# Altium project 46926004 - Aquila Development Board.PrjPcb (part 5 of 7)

## Sheet 225_Debug2.SchDoc: Aquila Development Board
size A3; Organization: Toradex Solutions Inc.; Address1: 6415 Northwest Drive; Address2: Mississauga, ON, L4V 1X1; Address3: Canada; SheetNumber: 11; SheetTotal: 34
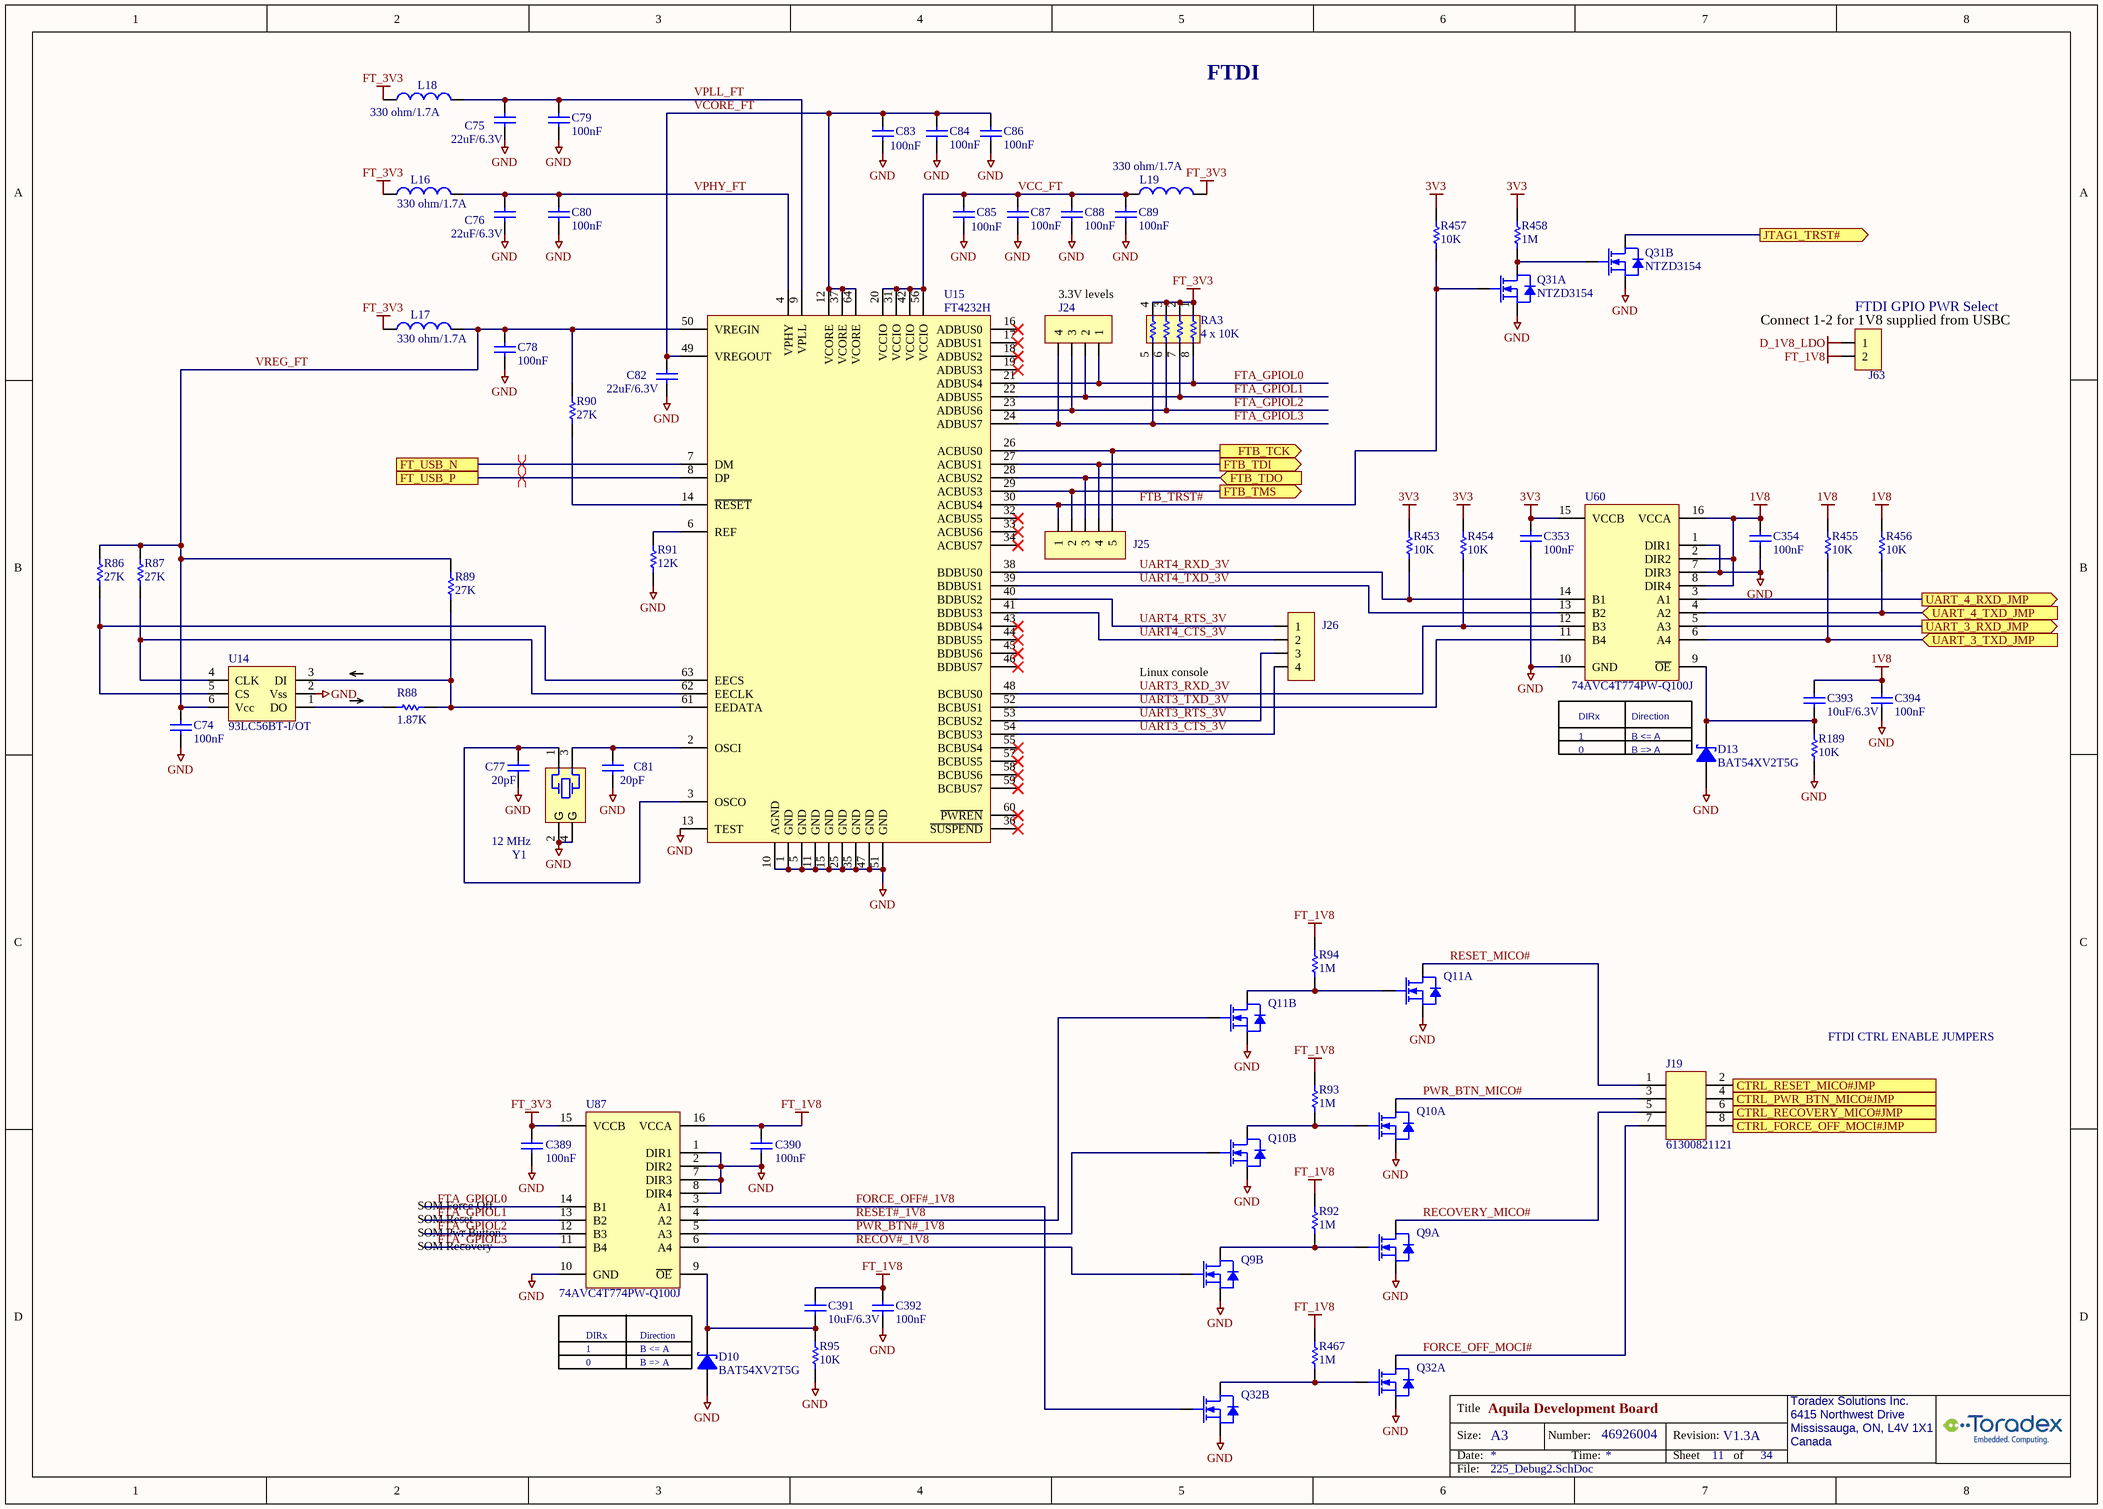
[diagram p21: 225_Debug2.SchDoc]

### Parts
C74  100nF  [C0402_CAPC1005L]
C75  22uF/6.3V  [C0402_CAPC1005L]
C76  22uF/6.3V  [C0402_CAPC1005L]
C77  value 20pF  [C0402_CAPC1005L]  (hidden comment: 1555-Cap-0402-20pF)
C78  100nF  [C0402_CAPC1005L]
C79  100nF  [C0402_CAPC1005L]
C80  100nF  [C0402_CAPC1005L]
C81  value 20pF  [C0402_CAPC1005L]  (hidden comment: 1555-Cap-0402-20pF)
C82  22uF/6.3V  [C0402_CAPC1005L]
C83  100nF  [C0402_CAPC1005L]
C84  100nF  [C0402_CAPC1005L]
C85  100nF  [C0402_CAPC1005L]
C86  100nF  [C0402_CAPC1005L]
C87  100nF  [C0402_CAPC1005L]
C88  100nF  [C0402_CAPC1005L]
C89  100nF  [C0402_CAPC1005L]
C353  100nF  [C0402_CAPC1005L]
C354  100nF  [C0402_CAPC1005L]
C389  100nF  [C0402_CAPC1005L]
C390  100nF  [C0402_CAPC1005L]
C391  value 10uF/6.3V  [C0402_CAPC1005L]  (hidden comment: 1646-Cap-0402-10uF/6.3V)
C392  100nF  [C0402_CAPC1005L]
C393  value 10uF/6.3V  [C0402_CAPC1005L]  (hidden comment: 1646-Cap-0402-10uF/6.3V)
C394  100nF  [C0402_CAPC1005L]
D10  BAT54XV2T5G  [SOD523_SC79]
D13  BAT54XV2T5G  [SOD523_SC79]
J19  61300821121  [WURTH_61300821121]
J24  000-Hdr-4pin  [HDR1X4]  (value not drawn)  (no BOM)
J25  000-Hdr-5pin  [HDR1X5]  (value not drawn)  (no BOM)
J26  000-Hdr-4pin  [HDR1X4]  (value not drawn)  (no BOM)
J63  67996-200HLF  [CON_HDR1X2]  (value not drawn)
L16  value 330 ohm/1.7A  [C/0603]  (hidden comment: 0405-Fer-0603-330ohm/1.7A)
L17  value 330 ohm/1.7A  [C/0603]  (hidden comment: 0405-Fer-0603-330ohm/1.7A)
L18  value 330 ohm/1.7A  [C/0603]  (hidden comment: 0405-Fer-0603-330ohm/1.7A)
L19  value 330 ohm/1.7A  [C/0603]  (hidden comment: 0405-Fer-0603-330ohm/1.7A)
Q9  NTZD3154  [SOT563]  (value not drawn)  (parts A,B of 2)
Q10  NTZD3154  [SOT563]  (value not drawn)  (parts A,B of 2)
Q11  NTZD3154  [SOT563]  (value not drawn)  (parts A,B of 2)
Q31  NTZD3154  [SOT563]  (parts A,B of 2)
Q32  NTZD3154  [SOT563]  (value not drawn)  (parts A,B of 2)
R86  value 27K  [R0402_RESC1005L]  (hidden comment: 1538-Res-0402-27k)
R87  value 27K  [R0402_RESC1005L]  (hidden comment: 1538-Res-0402-27k)
R88  value 1.87K  [R0402_RESC1005L]  (hidden comment: 1536-Res-0402-1.87K)
R89  value 27K  [R0402_RESC1005L]  (hidden comment: 1538-Res-0402-27k)
R90  value 27K  [R0402_RESC1005L]  (hidden comment: 1538-Res-0402-27k)
R91  value 12K  [R0402_RESC1005L]  (hidden comment: 1537-Res-0402-12K)
R92  value 1M  [R0402_RESC1005L]  (hidden comment: 1542-Res-0402-1M)
R93  value 1M  [R0402_RESC1005L]  (hidden comment: 1542-Res-0402-1M)
R94  value 1M  [R0402_RESC1005L]  (hidden comment: 1542-Res-0402-1M)
R95  value 10K  [R0402_RESC1005L]  (hidden comment: 1572-Res-0402-10K)
R189  value 10K  [R0402_RESC1005L]  (hidden comment: 1572-Res-0402-10K)
R453  value 10K  [R0402_RESC1005L]  (hidden comment: 1572-Res-0402-10K)
R454  value 10K  [R0402_RESC1005L]  (hidden comment: 1572-Res-0402-10K)
R455  value 10K  [R0402_RESC1005L]  (hidden comment: 1572-Res-0402-10K)
R456  value 10K  [R0402_RESC1005L]  (hidden comment: 1572-Res-0402-10K)
R457  value 10K  [R0402_RESC1005L]  (hidden comment: 1572-Res-0402-10K)
R458  value 1M  [R0402_RESC1005L]  (hidden comment: 1542-Res-0402-1M)
R467  value 1M  [R0402_RESC1005L]  (hidden comment: 1542-Res-0402-1M)
RA3  value 4 x 10K  [RESNET-1206-4]  (hidden comment: 1407-ResArr-1206-10K)
U14  93LC56BT-I/OT  [SOT23-6]
U15  FT4232H  [LQFP64_N]
U60  74AVC4T774PW-Q100J  [TSSOP16_NXP]
U87  74AVC4T774PW-Q100J  [TSSOP16]
Y1  value 12 MHz  [XTAL_CX3225]  (hidden comment: 0986-Xtal 12MHz 3.2x2.5mm)

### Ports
CTRL_FORCE_OFF_MOCI#JMP (out), CTRL_PWR_BTN_MICO#JMP (out), CTRL_RECOVERY_MICO#JMP (out), CTRL_RESET_MICO#JMP (out), FT_USB_N, FT_USB_P, FTB_TCK (out), FTB_TDI (out), FTB_TDO (in), FTB_TMS (out), JTAG1_TRST# (out), UART_3_RXD_JMP (out), UART_3_TXD_JMP (in), UART_4_RXD_JMP (out), UART_4_TXD_JMP (in)

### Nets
1V8: C354.2 C393.2 C394.2 R455.1 R456.1 U60.2(DIR2) U60.8(DIR4) U60.16(VCCA)
3V3: C353.2 R453.1 R454.1 R457.1 R458.1 U60.15(VCCB)
D_1V8_LDO: J63.1
FT_1V8: C390.2 C391.2 C392.2 J63.2 R92.1 R93.1 R94.1 R467.1 U87.16(VCCA)
FT_3V3: C389.2 L16.1 L17.1 L18.1 L19.1 RA3.1 RA3.2 RA3.3 RA3.4 U87.15(VCCB)
GND: C74.1 C75.1 C76.1 C77.2 C78.1 C79.1 C80.1 C81.2 C82.1 C83.1 C84.1 C85.1 C86.1 C87.1 C88.1 C89.1 C353.1 C354.1 C389.1 C390.1 C392.1 C394.1 D10.2(A) D13.2(A) Q9.1(S) Q9.4(S) Q10.1(S) Q10.4(S) Q11.1(S) Q11.4(S) Q31.1(S) Q31.4(S) Q32.1(S) Q32.4(S) R91.1 R95.2 R189.2 U14.2(Vss) U15.1(GND) U15.5(GND) U15.10(AGND) U15.11(GND) U15.13(TEST) U15.15(GND) U15.25(GND) U15.35(GND) U15.47(GND) U15.51(GND) U60.1(DIR1) U60.7(DIR3) U60.10(GND) U87.1(DIR1) U87.2(DIR2) U87.7(DIR3) U87.8(DIR4) U87.10(GND) Y1.2(GND) Y1.4(GND)
CTRL_FORCE_OFF_MOCI#JMP: J19.8 ; port CTRL_FORCE_OFF_MOCI#JMP
CTRL_PWR_BTN_MICO#JMP: J19.4 ; port CTRL_PWR_BTN_MICO#JMP
CTRL_RECOVERY_MICO#JMP: J19.6 ; port CTRL_RECOVERY_MICO#JMP
CTRL_RESET_MICO#JMP: J19.2 ; port CTRL_RESET_MICO#JMP
FORCE_OFF#_1V8: Q32.5(G) U87.3(A1)
FORCE_OFF_MOCI#: J19.7 Q32.6(D)
FT_USB_N: U15.7(DM) ; port FT_USB_N
FT_USB_P: U15.8(DP) ; port FT_USB_P
FTA_GPIOL0: J24.1 RA3.8 U15.21(ADBUS4) U87.14(B1)
FTA_GPIOL1: J24.2 RA3.7 U15.22(ADBUS5) U87.13(B2)
FTA_GPIOL2: J24.3 RA3.6 U15.23(ADBUS6) U87.12(B3)
FTA_GPIOL3: J24.4 RA3.5 U15.24(ADBUS7) U87.11(B4)
FTB_TCK: J25.5 U15.26(ACBUS0) ; port FTB_TCK
FTB_TDI: J25.4 U15.27(ACBUS1) ; port FTB_TDI
FTB_TDO: J25.3 U15.28(ACBUS2) ; port FTB_TDO
FTB_TMS: J25.2 U15.29(ACBUS3) ; port FTB_TMS
FTB_TRST#: J25.1 Q31.2(G) R457.2 U15.30(ACBUS4)
JTAG1_TRST#: Q31.3(D) ; port JTAG1_TRST#
PWR_BTN#_1V8: Q10.5(G) U87.5(A3)
PWR_BTN_MICO#: J19.3 Q10.6(D)
RECOV#_1V8: Q9.5(G) U87.6(A4)
RECOVERY_MICO#: J19.5 Q9.6(D)
RESET#_1V8: Q11.5(G) U87.4(A2)
RESET_MICO#: J19.1 Q11.6(D)
UART3_CTS_3V: J26.4 U15.54(BCBUS3)
UART3_RTS_3V: J26.3 U15.53(BCBUS2)
UART3_RXD_3V: R454.2 U15.48(BCBUS0) U60.12(B3)
UART3_TXD_3V: U15.52(BCBUS1) U60.11(B4)
UART4_CTS_3V: J26.2 U15.41(BDBUS3)
UART4_RTS_3V: J26.1 U15.40(BDBUS2)
UART4_RXD_3V: R453.2 U15.38(BDBUS0) U60.14(B1)
UART4_TXD_3V: U15.39(BDBUS1) U60.13(B2)
UART_3_RXD_JMP: U60.5(A3) ; port UART_3_RXD_JMP
UART_3_TXD_JMP: R455.2 U60.6(A4) ; port UART_3_TXD_JMP
UART_4_RXD_JMP: U60.3(A1) ; port UART_4_RXD_JMP
UART_4_TXD_JMP: R456.2 U60.4(A2) ; port UART_4_TXD_JMP
VCC_FT: C85.2 C87.2 C88.2 C89.2 L19.2 U15.20(VCCIO) U15.31(VCCIO) U15.42(VCCIO) U15.56(VCCIO)
VCORE_FT: C82.2 C83.2 C84.2 C86.2 U15.12(VCORE) U15.37(VCORE) U15.49(VREGOUT) U15.64(VCORE)
VPHY_FT: C76.2 C80.2 L16.2 U15.4(VPHY)
VPLL_FT: C75.2 C79.2 L18.2 U15.9(VPLL)
VREG_FT: C74.2 C78.2 L17.2 R86.1 R87.1 R89.1 R90.1 U14.6(Vcc) U15.50(VREGIN)
NetC77_1: C77.1 U15.3(OSCO) Y1.1
NetC81_1: C81.1 U15.2(OSCI) Y1.3
NetC391_1: C391.1 D10.1(K) R95.1 U87.9(~{OE})
NetC393_1: C393.1 D13.1(K) R189.1 U60.9(~{OE})
NetQ9_2: Q9.2(G) Q9.3(D) R92.2
NetQ10_2: Q10.2(G) Q10.3(D) R93.2
NetQ11_2: Q11.2(G) Q11.3(D) R94.2
NetQ31_5: Q31.5(G) Q31.6(D) R458.2
NetQ32_2: Q32.2(G) Q32.3(D) R467.2
NetR86_2: R86.2 U14.5(CS) U15.63(EECS)
NetR87_2: R87.2 U14.4(CLK) U15.62(EECLK)
NetR88_1: R88.1 R89.2 U14.3(DI) U15.61(EEDATA)
NetR88_2: R88.2 U14.1(DO)
NetR90_2: R90.2 U15.14(~{RESET})
NetR91_2: R91.2 U15.6(REF)

Not connected (* = marked no-connect by the designer): U15 16(ADBUS0)* 17(ADBUS1)* 18(ADBUS2)* 19(ADBUS3)* 32(ACBUS5)* 33(ACBUS6)* 34(ACBUS7)* 36(~{SUSPEND})* 43(BDBUS4)* 44(BDBUS5)* 45(BDBUS6)* 46(BDBUS7)* 55(BCBUS4)* 57(BCBUS5)* 58(BCBUS6)* 59(BCBUS7)* 60(~{PWREN})*

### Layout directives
differential pair; differential pair class USB_FT: FT_USB_N, FT_USB_P

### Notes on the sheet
- FTDI
- 3.3V levels
- (near J63) FTDI GPIO PWR Select
- (near J63) Connect 1-2 for 1V8 supplied from USBC
- Linux console
- (near U60) DIRx
- Direction
- 1
- 0
- B <= A
- (near D13) B => A
- (near J19) FTDI CTRL ENABLE JUMPERS
- SOM Pwr Button
- SOM Reset
- SOM Recovery
- SOM Force Off
- DIRx
- (near D10) Direction
- (near D10) B <= A
- (near D10) B => A

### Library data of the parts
C74 C78-C80 C83-C89 C353 C354 C389 C390 C392 C394 = 1566-Cap-0402-100nF/50V: (-55 to 125 DegC AEC) Cap Ceramic 0.1uF 50V X7R 10% 0402; MfrNo: GRT155R71H104KE01D; Mfr: Murata; Alt: CL05B104KB54PNC,GCM155R71H104ME02D,GCM155R71H104KE02D,GCM155R71H104KE02J; PN: 1566
C75 C76 C82 = 2404-Cap-0402-22uF/6.3V: (-55 to 85 DegC) CAP CER 22UF 6.3V 20% X5R 0402; MfrNo: GRM155R60J226ME11D; Mfr: Murata; PN: 2404
C77 C81 = 1555-Cap-0402-20pF: (-55 to 125 DegC AEC) CAP CER 20PF 5% 50V C0G/NPO 0402; Mfr: Samsung; MfrNo: CL05C200JB51PNC; Alt: GCM1555C1H200JA16D,GCM1555C1H200GA16D; PN: 1555
C391 C393 = 1646-Cap-0402-10uF/6.3V: (-55 to 85 DegC) CAP CER 10UF 6.3V 20% X5R 0402; MfrNo: GRM155R60J106ME44D; Mfr: Murata; Alt: GRM155R60J106ME47D,C0402C106M9PACTU,04026D106MAT2A; PN: 1646
D10 D13 = 1670-BAT54XV2T5G: (-55 to 125 DegC) DIODE SCHOTTKY 30V 200MA SOD523 / SC79; Mfr: ON Semiconductor; PN: 1670
J19 = 2532-Conn-Hdr 2x4 2.54MM: (-40 to 105 DegC) CONN HEADER MALE VERT 2x4 8POS 2.54MM TH; Mfr: Wurth Electronics; PN: 2532
J24 J26 = 000-Hdr-4pin: Header, 4-Pin; Note: PCB footprint only, no parts to buy or assemble
J25 = 000-Hdr-5pin: Header, 5-Pin; Note: PCB footprint only, no parts to buy or assemble
J63 = 1250-Conn-Hdr-1x2 TH Vert: (-40 to 85 DegC) CONN HDR VERT 1x2 2pos 2.54mm 0.1in Gold no-shroud; Mfr: Amphenol FCI; PN: 1250
L16-L19 = 0405-Fer-0603-330ohm/1.7A: (-55 to 125 DegC) FERRITE BEAD 330 OHM 0603 1.7A 80mohm, typ 48mohm; Mfr: TDK Corporation; MfrNo: MPZ1608S331ATA00; PN: 405; TR: 445-5221-2-ND; DR: 445-5221-6-ND; DR2: 810-MPZ1608S331ATA00
Q9-Q11 Q31 Q32 = 1146-NTZD3154NT1G: (-55 to 150 DegC) MOSFET 2N-CH (dual) 20V 0.54A SOT-563 1.6x1.6mm Vth:1V Ron typ:400m@4.5V, 500m@2.5V, 700m@1.8V; Mfr: ON Semiconductor; PN: 1146; Alt: NTZD3154NT5G,PMDT290UNE,115
R86 R87 R89 R90 = 1538-Res-0402-27k: (-55 to 155 DegC AEC) RES 27K OHM 1% 1/16W 100ppm 0402; Mfr: Stackpole Electronics; MfrNo: RMCF0402FT27K0; PN: 1538; Alt: AC0402FR-0727KL,CRGCQ0402F27K
R88 = 1536-Res-0402-1.87K: (-55 to 155 DegC AEC) RES 1.87K OHM 1% 1/16W 100ppm 0402; MfrNo: RMCF0402FT1K87; Mfr: Stackpole Electronics; Alt: AC0402FR-071K87L,RK73H1ETTP1871F,ERJ-2RKF1871X; PN: 1536
R91 = 1537-Res-0402-12K: (-55 to 155 DegC AEC) RES 12K OHM 1% 1/16W 100ppm 0402; Mfr: Stackpole Electronics; MfrNo: RMCF0402FT12K0; Alt: AC0402FR-0712KL,CRGCQ0402F12K; PN: 1537
R92-R94 R467 = 1542-Res-0402-1M: (-55 to 155 DegC AEC) RES 1M OHM 1% 1/16W 100ppm 0402; Mfr: Stackpole Electronics; MfrNo: RMCF0402FT1M00; PN: 1542; Alt: AC0402FR-071ML,CRGCQ0402F1M0,RK73H1ETTP1004F
R95 R189 R453-R457 = 1572-Res-0402-10K: (-55 to 155 DegC AEC) RES 10K OHM 1% 1/16W 100ppm 0402; Mfr: Stackpole Electronics; MfrNo: RMCF0402FT10K0; Alt: AC0402FR-0710KL,AC0402FR-1310KL,CRGCQ0402F10K; PN: 1572
R458 = 1542-Res-0402-1M: (-55 to 155 DegC AEC) RES 1M OHM 1% 1/16W 100ppm 0402; Mfr: Stackpole Electronics; MfrNo: RMCF0402FT1M00; Alt: AC0402FR-071ML,CRGCQ0402F1M0,RK73H1ETTP1004F; PN: 1542
RA3 = 1407-ResArr-1206-10K: (-55 to 125 DegC) RES ARRAY 4 RES 10K 1% 200ppm 1206; Mfr: Yageo; MfrNo: TC164-FR-0710KL; PN: 1407; Alt: YC164-FR-0710KL
U14 = 1263-93LC56BT: (-40 to 85 DegC) IC EEPROM 2KBit 128x16 SPI 2MHz SOT23-6 2.5-5.5V; Mfr: Microchip; PN: 1263
U15 = 0956-FT4232H: (-40 to 85 DegC) IC USB HS QUAD UART/SYNC 64-LQFP; MfrNo: FT4232HL-REEL; Mfr: FTDI, Future Technology Devices International Ltd; PN: 956
U60 U87 = 1597-74AVC4T774: (-40 to 125 DegC AEC) IC Translator 4ch BiDirer 0.8 to 3.6V 380MBps 16TSSOP; Mfr: Nexperia; PN: 1597; Alt: 74AVC4T774PWJ
Y1 = 0986-Xtal 12MHz 3.2x2.5mm: (-40 to 85 DegC) CRYSTAL 12MHZ 10PF SMD +-30ppm +-20ppm 3.2x2.5mm Caps:16pF; Mfr: Abracon LLC; MfrNo: ABM8G-106-12.000MHZ-T; PN: 986

## Sheet 227_JTAG.SchDoc: Aquila Development Board
size Letter; Organization: Toradex Solutions Inc.; Address1: 6415 Northwest Drive; Address2: Mississauga, ON, L4V 1X1; Address3: Canada; SheetNumber: 12; SheetTotal: 34
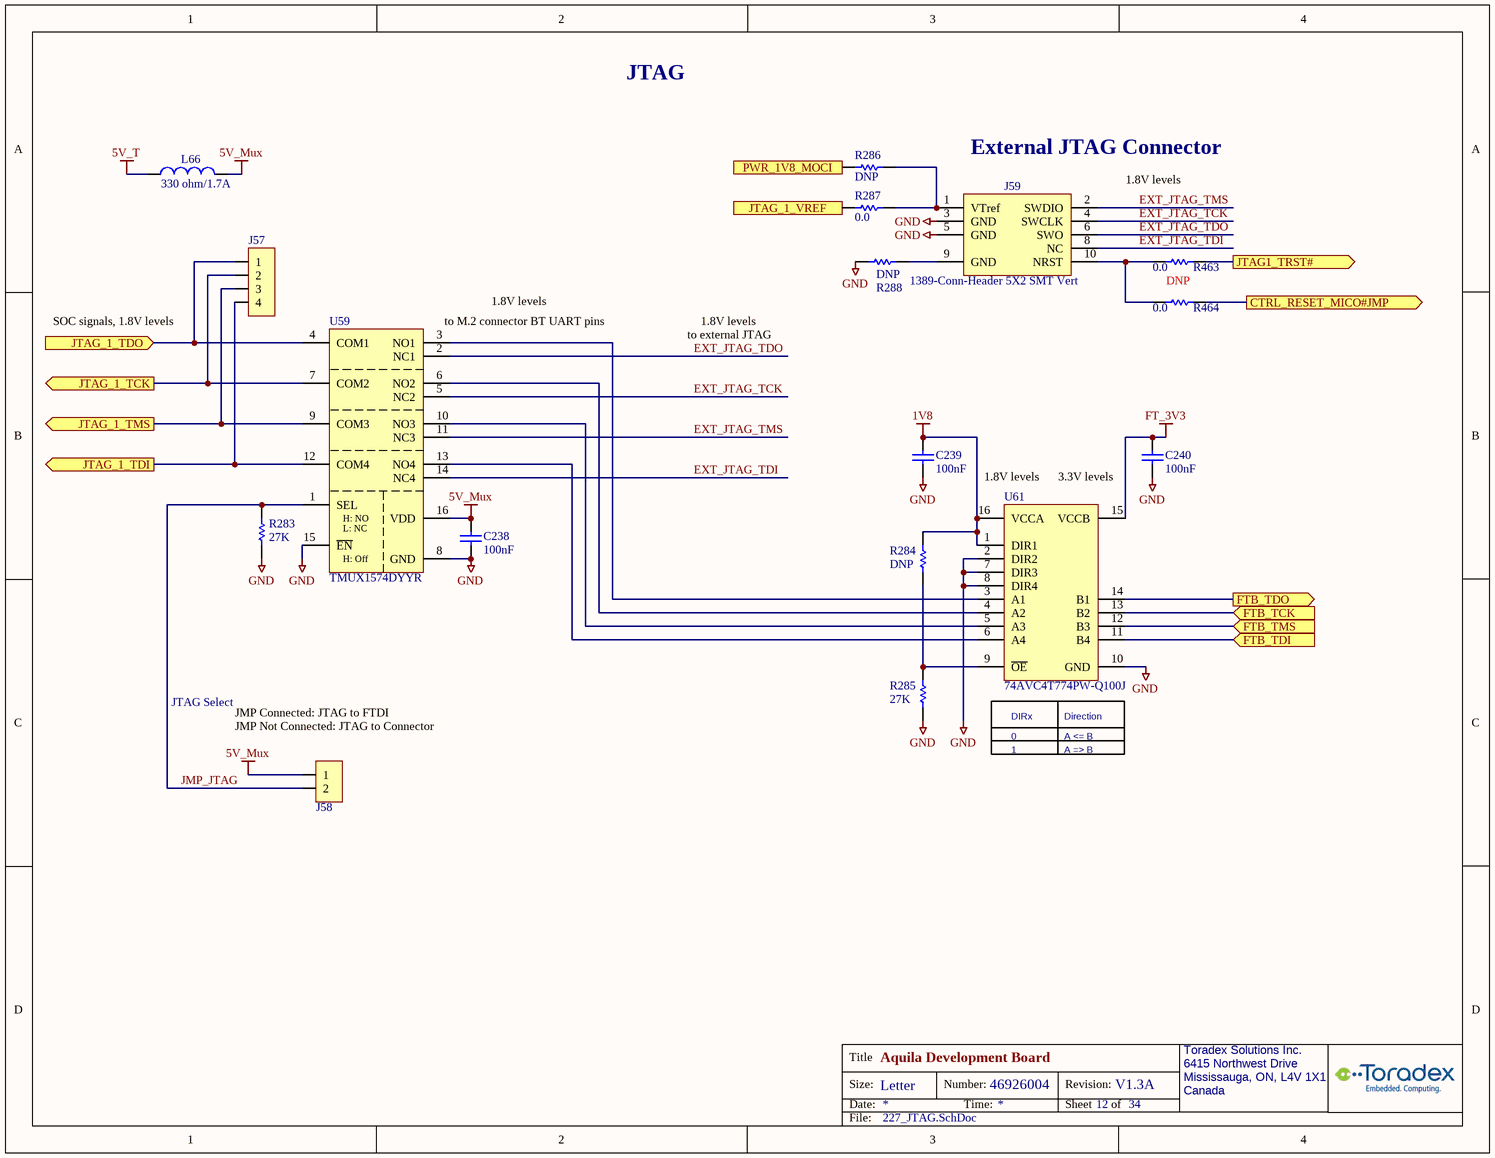
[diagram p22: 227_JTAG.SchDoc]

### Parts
C238  100nF  [C0402_CAPC1005L]
C239  100nF  [C0402_CAPC1005L]
C240  100nF  [C0402_CAPC1005L]
J57  000-Hdr-4pin  [HDR1X4]  (value not drawn)  (no BOM)
J58  67996-200HLF  [CON_HDR1X2]  (value not drawn)
J59  1389-Conn-Header 5X2 SMT Vert  [SAMTEC_FTSH-105-01-L-DV-007]
L66  value 330 ohm/1.7A  [C/0603]  (hidden comment: 0405-Fer-0603-330ohm/1.7A)
R283  value 27K  [R0402_RESC1005L]  (hidden comment: 1538-Res-0402-27k)
R284  value DNP  [R/0603]  (hidden comment: 0000-Res-0603-DNP)
R285  value 27K  [R0402_RESC1005L]  (hidden comment: 1538-Res-0402-27k)
R286  value DNP  [R/0603]  (hidden comment: 0000-Res-0603-DNP)
R287  value 0.0  [R/0603]  (hidden comment: 0195-Res-0603-0.0ohm)
R288  value DNP  [R/0603]  (hidden comment: 0000-Res-0603-DNP)
R463  value 0.0  [R/0603]  (hidden comment: 0195-Res-0603-0.0ohm)  (no BOM)
R464  value 0.0  [R/0603]  (hidden comment: 0195-Res-0603-0.0ohm)
U59  TMUX1574DYYR  [SOP50P326X110-16N]
U61  74AVC4T774PW-Q100J  [TSSOP16_NXP]

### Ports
CTRL_RESET_MICO#JMP (out), FTB_TCK (in), FTB_TDI (in), FTB_TDO (out), FTB_TMS (in), JTAG1_TRST# (out), JTAG_1_TCK (out), JTAG_1_TDI (out), JTAG_1_TDO (in), JTAG_1_TMS (out), JTAG_1_VREF (in), PWR_1V8_MOCI (in)

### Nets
1V8: C239.2 R284.2 U61.1(DIR1) U61.16(VCCA)
5V_Mux: C238.2 J58.1 L66.2 U59.16(VDD)
5V_T: L66.1
FT_3V3: C240.2 U61.15(VCCB)
GND: C238.1 C239.1 C240.1 J59.3(GND) J59.5(GND) R283.1 R285.1 R288.2 U59.8(GND) U59.15(~{EN}) U61.2(DIR2) U61.7(DIR3) U61.8(DIR4) U61.10(GND)
CTRL_RESET_MICO#JMP: R464.1 ; port CTRL_RESET_MICO#JMP
EXT_JTAG_TCK: J59.4(SWCLK) U59.5(NC2)
EXT_JTAG_TDI: J59.8(NC) U59.14(NC4)
EXT_JTAG_TDO: J59.6(SWO) U59.2(NC1)
EXT_JTAG_TMS: J59.2(SWDIO) U59.11(NC3)
FTB_TCK: U61.13(B2) ; port FTB_TCK
FTB_TDI: U61.11(B4) ; port FTB_TDI
FTB_TDO: U61.14(B1) ; port FTB_TDO
FTB_TMS: U61.12(B3) ; port FTB_TMS
JMP_JTAG: J58.2 R283.2 U59.1(SEL)
JTAG1_TRST#: R463.1 ; port JTAG1_TRST#
JTAG_1_TCK: J57.2 U59.7(COM2) ; port JTAG_1_TCK
JTAG_1_TDI: J57.4 U59.12(COM4) ; port JTAG_1_TDI
JTAG_1_TDO: J57.1 U59.4(COM1) ; port JTAG_1_TDO
JTAG_1_TMS: J57.3 U59.9(COM3) ; port JTAG_1_TMS
JTAG_1_VREF: R287.2 ; port JTAG_1_VREF
PWR_1V8_MOCI: R286.2 ; port PWR_1V8_MOCI
NetJ59_1: J59.1(VTref) R286.1 R287.1
NetJ59_9: J59.9(GND) R288.1
NetJ59_10: J59.10(NRST) R463.2 R464.2
NetR284_1: R284.1 R285.2 U61.9(~{OE})
NetU59_3: U59.3(NO1) U61.3(A1)
NetU59_6: U59.6(NO2) U61.4(A2)
NetU59_10: U59.10(NO3) U61.5(A3)
NetU59_13: U59.13(NO4) U61.6(A4)

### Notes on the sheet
- JTAG
- (near J59) External JTAG Connector
- 1.8V levels
- DNP
- (near J57) SOC signals, 1.8V levels
- (near U59) to M.2 connector BT UART pins
- to external JTAG
- (near U61) 1.8V levels
- 3.3V levels
- JTAG Select
- (near U61) DIRx
- (near U61) Direction
- JMP Connected: JTAG to FTDI
- (near J58) JMP Not Connected: JTAG to Connector
- 0
- 1
- A <= B
- A => B

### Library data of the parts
C238-C240 = 1566-Cap-0402-100nF/50V: as C74 on sheet 225_Debug2
J57 = 000-Hdr-4pin: as J24 on sheet 225_Debug2
J58 = 1250-Conn-Hdr-1x2 TH Vert: as J63 on sheet 225_Debug2
J59 = 1389-Conn-Header 5X2 SMT Vert: (-55 to 125 DegC) CONN HEADER VERT 9POS 2x5 1.27MM JTAG; Mfr: Samtec; MfrNo: FTSH-105-01-L-DV-007-K; PN: 1389
L66 = 0405-Fer-0603-330ohm/1.7A: as L16-L19 on sheet 225_Debug2
R283 R285 = 1538-Res-0402-27k: as R86 on sheet 225_Debug2
R284 R286 R288 = 0000-Res-0603-DNP: RES 0603
R287 R463 R464 = 0195-Res-0603-0.0ohm: (-55 to 155 DegC) RES 0.0 OHM 1/10W JUMP 0603; Mfr: Samsung; MfrNo: RC1608J000CS; Alt: 311-0.0GRCT-ND; Alt2: A106051CT-ND; PN: 195; TR: 1276-3510-2-ND
U59 = 1847B-TMUX1574: (-40 to 125 DegC) IC Protected Analog SW 4CH-DPDT (4 Switches), 1.5-5.5V, R:2ohm, 4.5ohm max, 2GHz 7pF 1.8Vc with pull down SOT23-16 4.2x2; Mfr: Texas Instruments; PN: 1847
U61 = 1597-74AVC4T774: as U60 on sheet 225_Debug2

## Sheet 215_Translators2.SchDoc: Aquila Development Board
size Letter; Organization: Toradex Solutions Inc.; Address1: 6415 Northwest Drive; Address2: Mississauga, ON, L4V 1X1; Address3: Canada; SheetNumber: 9; SheetTotal: 34
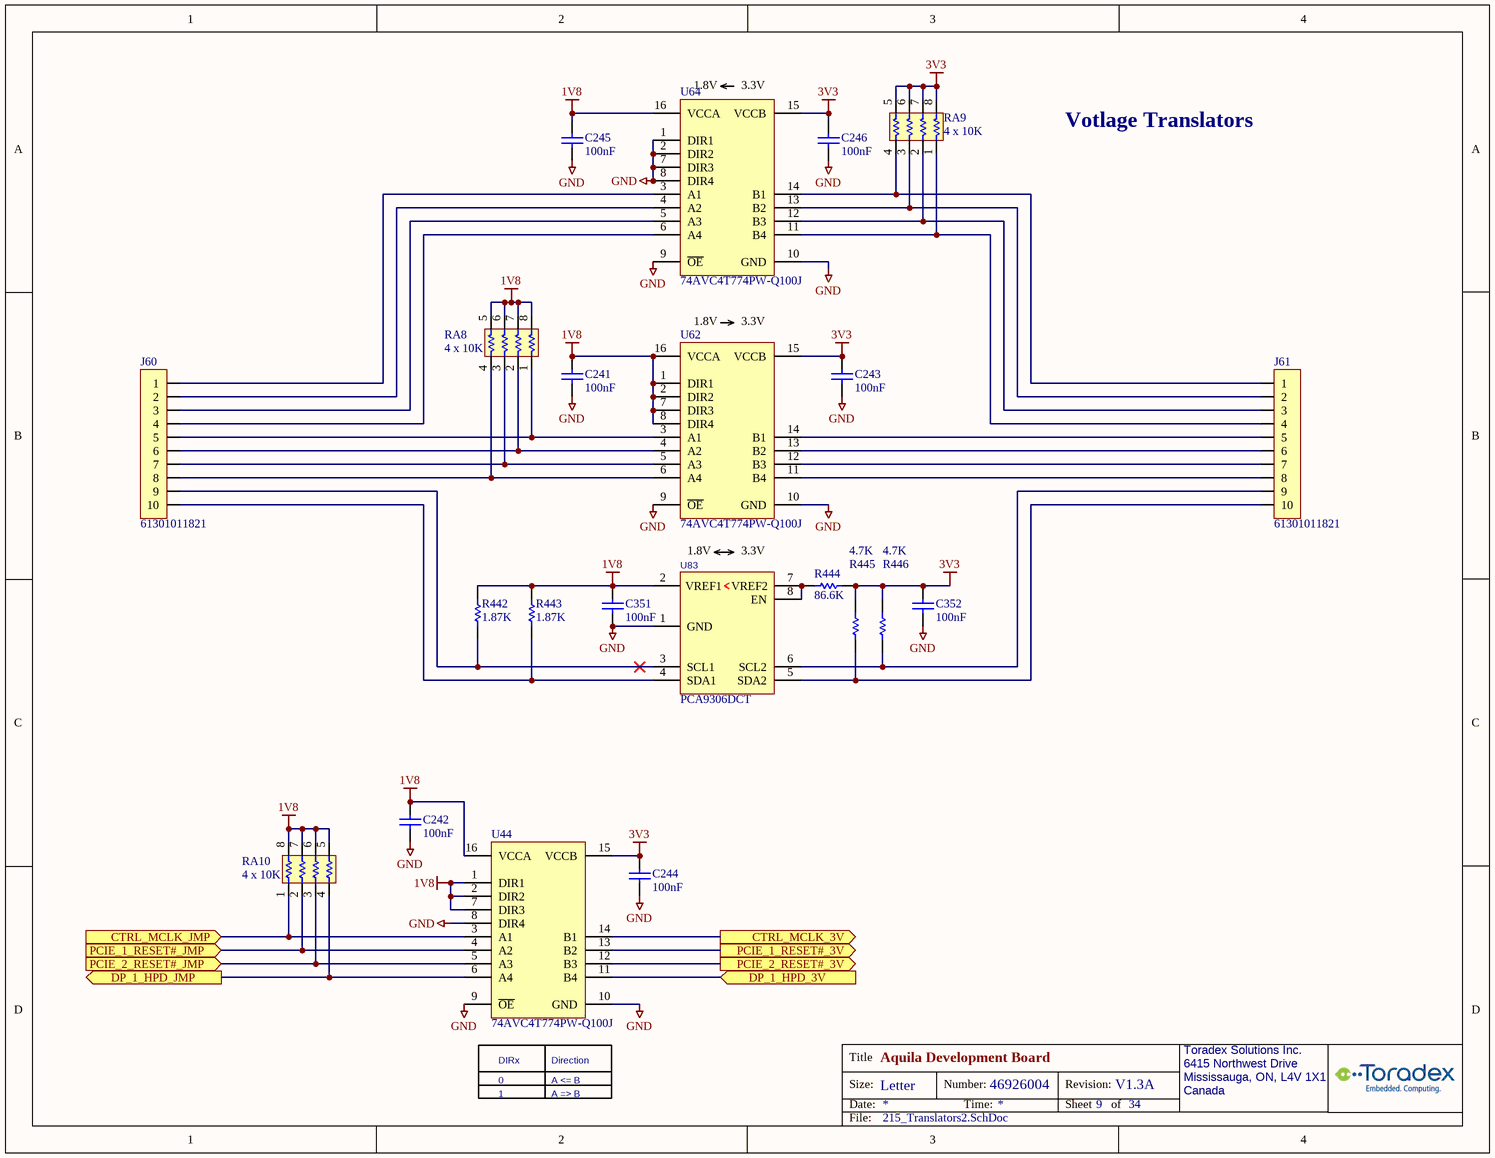
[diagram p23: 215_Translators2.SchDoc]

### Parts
C241  100nF  [C0402_CAPC1005L]
C242  100nF  [C0402_CAPC1005L]
C243  100nF  [C0402_CAPC1005L]
C244  100nF  [C0402_CAPC1005L]
C245  100nF  [C0402_CAPC1005L]
C246  100nF  [C0402_CAPC1005L]
C351  100nF  [C0402_CAPC1005L]
C352  100nF  [C0402_CAPC1005L]
J60  61301011821  [WURTH_61301011821]
J61  61301011821  [WURTH_61301011821]
R442  value 1.87K  [R0402_RESC1005L]  (hidden comment: 1536-Res-0402-1.87K)
R443  value 1.87K  [R0402_RESC1005L]  (hidden comment: 1536-Res-0402-1.87K)
R444  value 86.6K  [R0402_RESC1005L]  (hidden comment: 1539-Res-0402-86.6k)
R445  value 4.7K  [R0402_RESC1005L]  (hidden comment: 2233-Res-0402-4.7K)
R446  value 4.7K  [R0402_RESC1005L]  (hidden comment: 2233-Res-0402-4.7K)
RA8  value 4 x 10K  [RESNET-1206-4]  (hidden comment: 1407-ResArr-1206-10K)
RA9  value 4 x 10K  [RESNET-1206-4]  (hidden comment: 1407-ResArr-1206-10K)
RA10  value 4 x 10K  [RESNET-1206-4]  (hidden comment: 1407-ResArr-1206-10K)
U44  74AVC4T774PW-Q100J  [TSSOP16_NXP]
U62  74AVC4T774PW-Q100J  [TSSOP16_NXP]
U64  74AVC4T774PW-Q100J  [TSSOP16_NXP]
U83  PCA9306DCT  [TSSO3x5-G8/X.35]

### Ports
CTRL_MCLK_3V (out), CTRL_MCLK_JMP (in), DP_1_HPD_3V (in), DP_1_HPD_JMP (out), PCIE_1_RESET#_3V (out), PCIE_1_RESET#_JMP (in), PCIE_2_RESET#_3V (out), PCIE_2_RESET#_JMP (in)

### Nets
1V8: C241.2 C242.2 C245.2 C351.2 R442.1 R443.1 RA8.5 RA8.6 RA8.7 RA8.8 RA10.5 RA10.6 RA10.7 RA10.8 U44.1(DIR1) U44.2(DIR2) U44.7(DIR3) U44.16(VCCA) U62.1(DIR1) U62.2(DIR2) U62.7(DIR3) U62.8(DIR4) U62.16(VCCA) U64.16(VCCA) U83.2(VREF1)
3V3: C243.2 C244.2 C246.2 C352.2 R444.1 R445.1 R446.1 RA9.5 RA9.6 RA9.7 RA9.8 U44.15(VCCB) U62.15(VCCB) U64.15(VCCB)
GND: C241.1 C242.1 C243.1 C244.1 C245.1 C246.1 C351.1 C352.1 U44.8(DIR4) U44.9(~{OE}) U44.10(GND) U62.9(~{OE}) U62.10(GND) U64.1(DIR1) U64.2(DIR2) U64.7(DIR3) U64.8(DIR4) U64.9(~{OE}) U64.10(GND) U83.1(GND)
CTRL_MCLK_3V: U44.14(B1) ; port CTRL_MCLK_3V
CTRL_MCLK_JMP: RA10.1 U44.3(A1) ; port CTRL_MCLK_JMP
DP_1_HPD_3V: U44.11(B4) ; port DP_1_HPD_3V
DP_1_HPD_JMP: RA10.4 U44.6(A4) ; port DP_1_HPD_JMP
PCIE_1_RESET#_3V: U44.13(B2) ; port PCIE_1_RESET#_3V
PCIE_1_RESET#_JMP: RA10.2 U44.4(A2) ; port PCIE_1_RESET#_JMP
PCIE_2_RESET#_3V: U44.12(B3) ; port PCIE_2_RESET#_3V
PCIE_2_RESET#_JMP: RA10.3 U44.5(A3) ; port PCIE_2_RESET#_JMP
NetJ60_1: J60.1 U64.3(A1)
NetJ60_2: J60.2 U64.4(A2)
NetJ60_3: J60.3 U64.5(A3)
NetJ60_4: J60.4 U64.6(A4)
NetJ60_5: J60.5 RA8.1 U62.3(A1)
NetJ60_6: J60.6 RA8.2 U62.4(A2)
NetJ60_7: J60.7 RA8.3 U62.5(A3)
NetJ60_8: J60.8 RA8.4 U62.6(A4)
NetJ60_9: J60.9 R442.2 U83.3(SCL1)
NetJ60_10: J60.10 R443.2 U83.4(SDA1)
NetJ61_1: J61.1 RA9.4 U64.14(B1)
NetJ61_2: J61.2 RA9.3 U64.13(B2)
NetJ61_3: J61.3 RA9.2 U64.12(B3)
NetJ61_4: J61.4 RA9.1 U64.11(B4)
NetJ61_5: J61.5 U62.14(B1)
NetJ61_6: J61.6 U62.13(B2)
NetJ61_7: J61.7 U62.12(B3)
NetJ61_8: J61.8 U62.11(B4)
NetJ61_9: J61.9 R446.2 U83.6(SCL2)
NetJ61_10: J61.10 R445.2 U83.5(SDA2)
NetR444_2: R444.2 U83.7(VREF2) U83.8(EN)

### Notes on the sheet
- (near U64) 1.8V
- (near U64) 3.3V
- Votlage Translators
- (near U62) 1.8V
- (near U62) 3.3V
- 1.8V
- 3.3V
- 0
- (near U44) DIRx
- 1
- (near U44) Direction
- A <= B
- A => B

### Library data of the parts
C241-C246 C351 C352 = 1566-Cap-0402-100nF/50V: as C74 on sheet 225_Debug2
J60 J61 = 2202-Conn-Hdr 1x10 2.54MM F: (-40 to 105 DegC) CONN HEADER FEMALE VERT 1x10 10POS 2.54MM TH; Mfr: Wurth Electronics; PN: 2202
R442 R443 = 1536-Res-0402-1.87K: as R88 on sheet 225_Debug2
R444 = 1539-Res-0402-86.6k: (-55 to 155 DegC AEC) RES 86.6K OHM 1% 1/16W 100ppm 0402; Mfr: Stackpole Electronics; MfrNo: RMCF0402FT86K6; Alt: AC0402FR-0786K6L,RK73H1ETTP8662F,ERJ-2RKF8662X; PN: 1539
R445 R446 = 2233-Res-0402-4.7K: (-55 to 155 DegC) RES 4.70K OHM 1/16W 1% 0402 100ppm; MfrNo: RC0402FR-074K7L; Mfr: Yageo; PN: 2233
RA8-RA10 = 1407-ResArr-1206-10K: as RA3 on sheet 225_Debug2
U44 U62 U64 = 1597-74AVC4T774: as U60 on sheet 225_Debug2
U83 = 0972-PCA9306DCT: (-40 to 85 DegC) IC TRANSLTR BIDIRECTIONAL I2C SM8; MfrNo: PCA9306DCTR; Mfr: Texas Instruments; PN: 972

## Sheet 050_Block_Diagram.SchDoc: Aquila Development Board
size A3 portrait; Organization: Toradex Solutions Inc.; Address1: 6415 Northwest Drive; Address2: Mississauga, ON, L4V 1X1; Address3: Canada; SheetNumber: 2; SheetTotal: 34
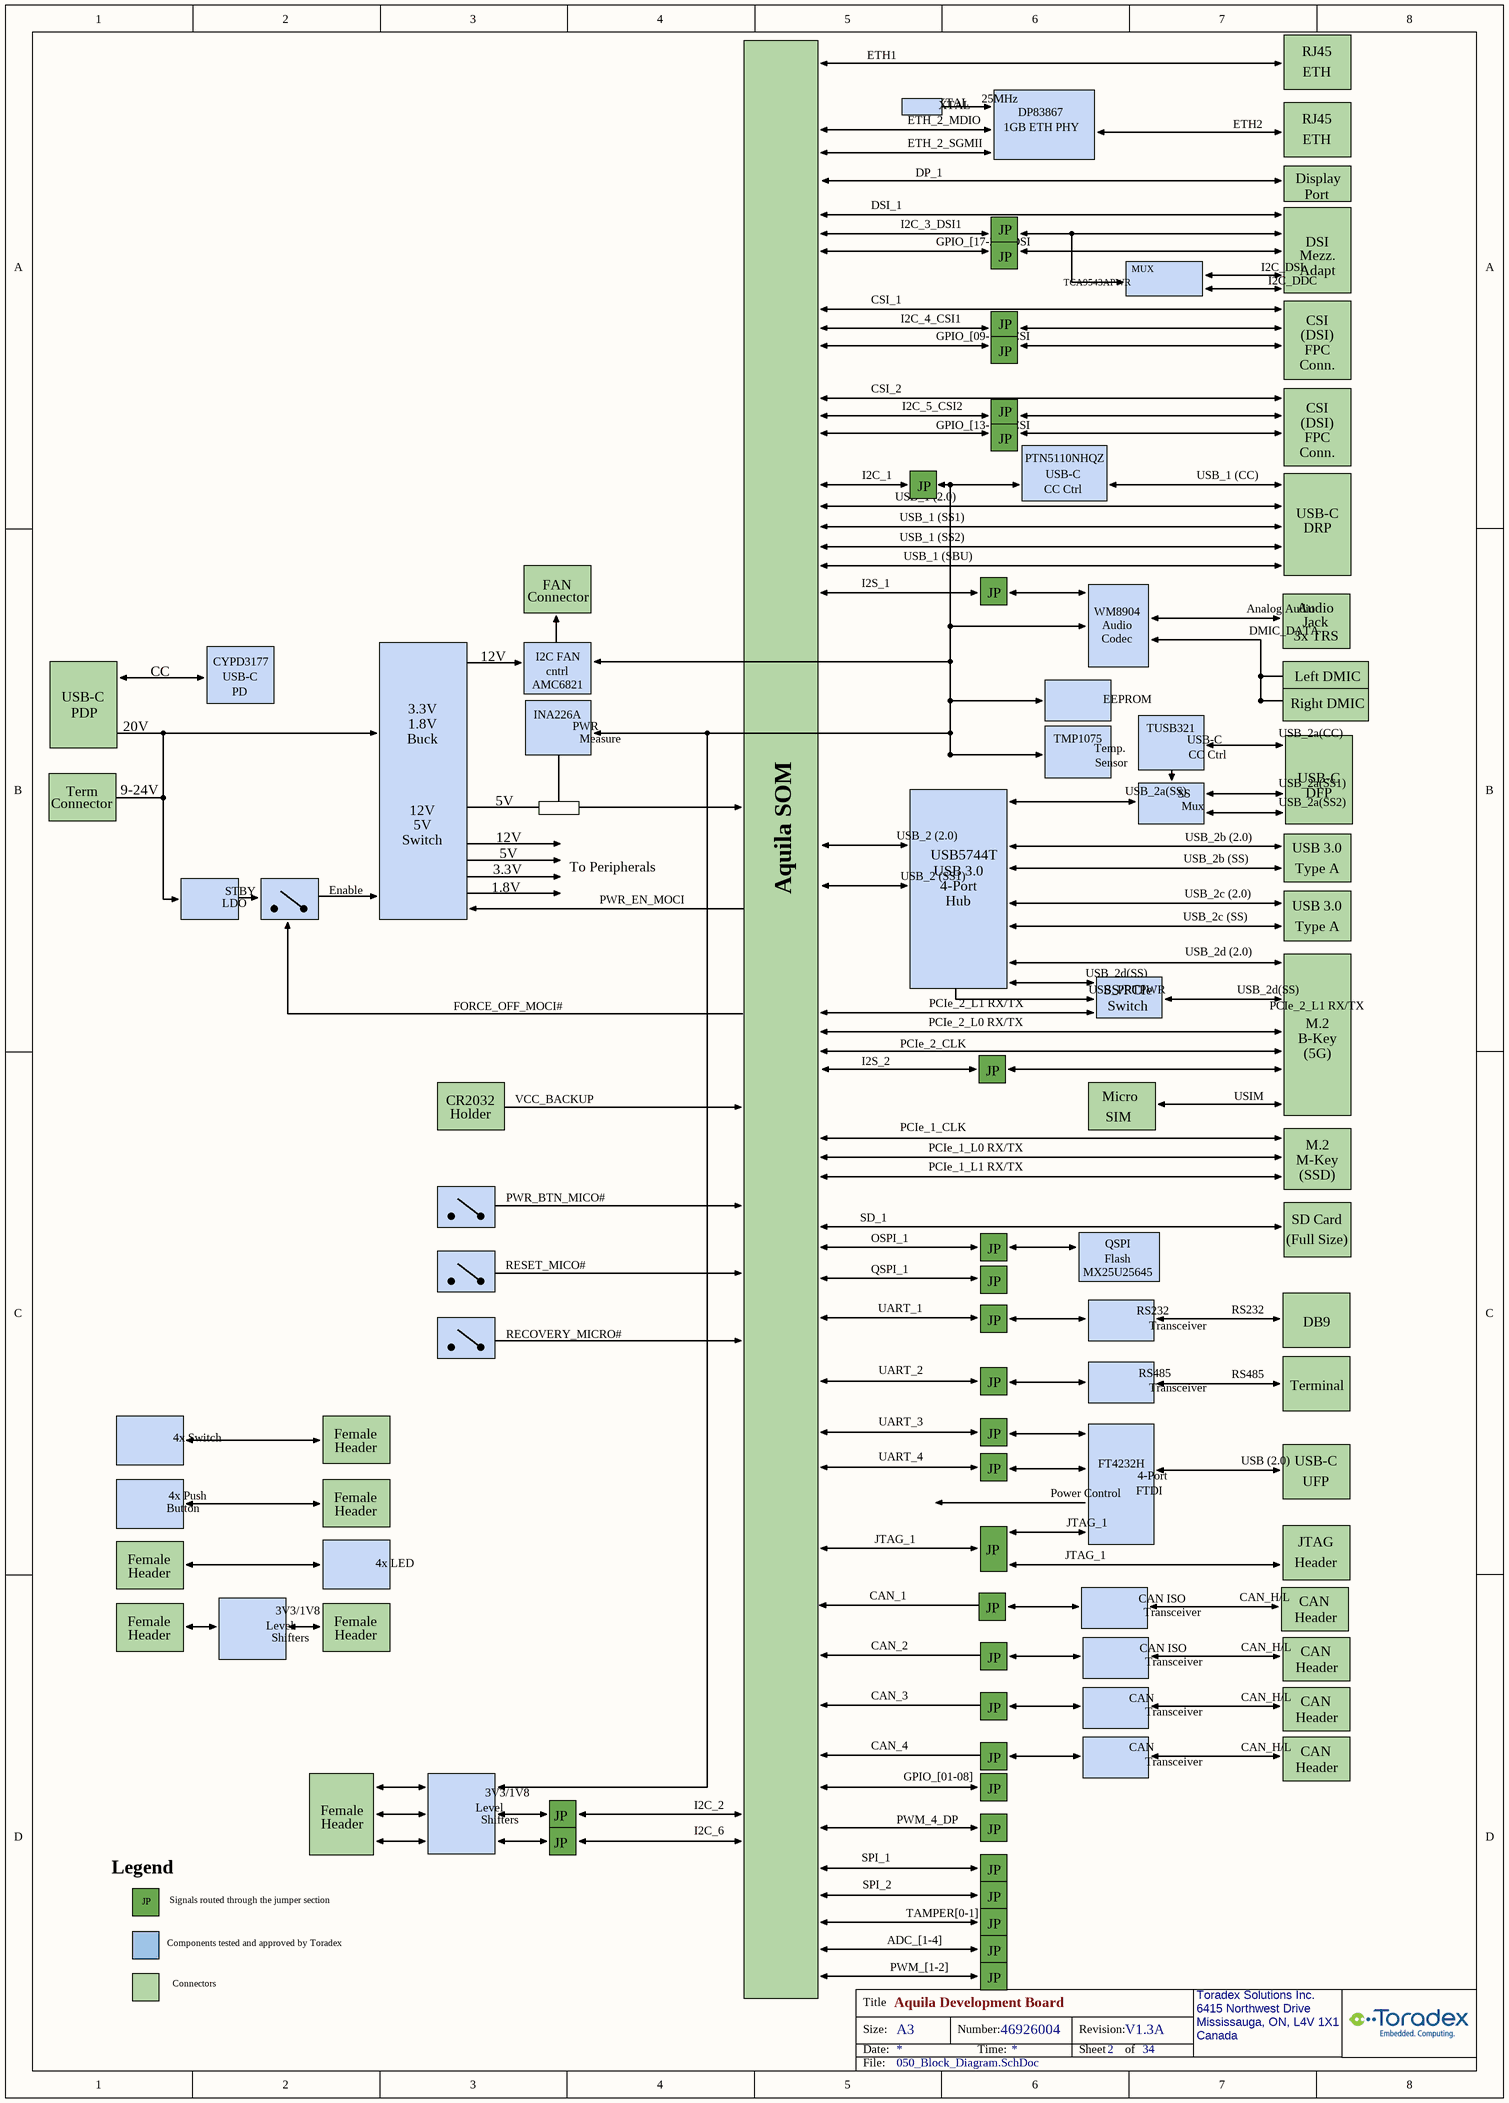
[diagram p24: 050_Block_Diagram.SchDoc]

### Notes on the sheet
- ETH1
- 25MHz
- RJ45
- ETH
- ETH_2_MDIO
- ETH_2_SGMII
- XTAL
- DP83867
- 1GB ETH PHY
- ETH2
- Display
- DSI_1
- I2C_3_DSI1
- DP_1
- JP
- Port
- DSI
- CSI_1
- GPIO_[17-20]_DSI
- TCA9543APWR
- MUX
- I2C_DSI
- I2C_DDC
- Mezz.
- Adapt
- I2C_4_CSI1
- GPIO_[09-12]_CSI
- (DSI)
- FPC
- Conn.
- CSI
- CSI_2
- I2C_5_CSI2
- GPIO_[13-16]_CSI
- I2C_1
- USB_1 (2.0)
- USB-C
- CC Ctrl
- PTN5110NHQZ
- USB_1 (CC)
- FAN
- USB_1 (SS2)
- USB_1 (SS1)
- USB_1 (SBU)
- DRP
- 12V
- Connector
- I2S_1
- Audio
- Codec
- WM8904
- Analog Audio
- DMIC_DATA
- Jack
- 3x TRS
- PDP
- CC
- PD
- CYPD3177
- 3.3V
- I2C FAN
- cntrl
- AMC6821
- EEPROM
- Left DMIC
- Right DMIC
- Term
- 20V
- 9-24V
- 1.8V
- Buck
- INA226A
- PWR
- Measure
- TMP1075
- Temp.
- Sensor
- TUSB321
- USB_2a(CC)
- 5V
- Switch
- Aquila SOM
- USB_2 (2.0)
- USB_2a(SS)
- SS
- Mux
- USB_2b (2.0)
- USB_2a(SS1)
- USB_2a(SS2)
- USB 3.0
- DFP
- LDO
- STBY
- Enable
- To Peripherals
- PWR_EN_MOCI
- USB_2 (SS1)
- USB5744T
- 4-Port
- Hub
- USB_2b (SS)
- USB_2c (2.0)
- Type A
- USB_2d(SS)
- SS/PCIe
- USB_2c (SS)
- USB_2d (2.0)
- FORCE_OFF_MOCI#
- PCIe_2_CLK
- PCIe_2_L0 RX/TX
- PCIe_2_L1 RX/TX
- USB_PRTPWR
- B-Key
- M.2
- (5G)
- CR2032
- Holder
- VCC_BACKUP
- I2S_2
- SIM
- Micro
- USIM
- PCIe_1_CLK
- PCIe_1_L0 RX/TX
- PCIe_1_L1 RX/TX
- M-Key
- (SSD)
- PWR_BTN_MICO#
- SD_1
- OSPI_1
- QSPI
- Flash
- SD Card
- (Full Size)
- RESET_MICO#
- QSPI_1
- UART_1
- MX25U25645
- RS232
- DB9
- RECOVERY_MICRO#
- UART_2
- RS485
- Transceiver
- Terminal
- 4x Switch
- Female
- Header
- UART_3
- Button
- 4x Push
- UART_4
- Power Control
- FT4232H
- FTDI
- USB (2.0)
- UFP
- 4x LED
- JTAG_1
- CAN
- JTAG
- Level
- Shifters
- 3V3/1V8
- CAN_1
- CAN_2
- CAN ISO
- CAN_H/L
- CAN_3
- CAN_4
- GPIO_[01-08]
- Legend
- I2C_2
- I2C_6
- PWM_4_DP
- Signals routed through the jumper section
- SPI_1
- SPI_2
- TAMPER[0-1]
- Connectors
- Components tested and approved by Toradex
- ADC_[1-4]
- PWM_[1-2]

## Sheet 800_Jumpers.SchDoc: Aquila Development Board
size A3; Organization: Toradex Solutions Inc.; Address1: 6415 Northwest Drive; Address2: Mississauga, ON, L4V 1X1; Address3: Canada; SheetNumber: 32; SheetTotal: 34
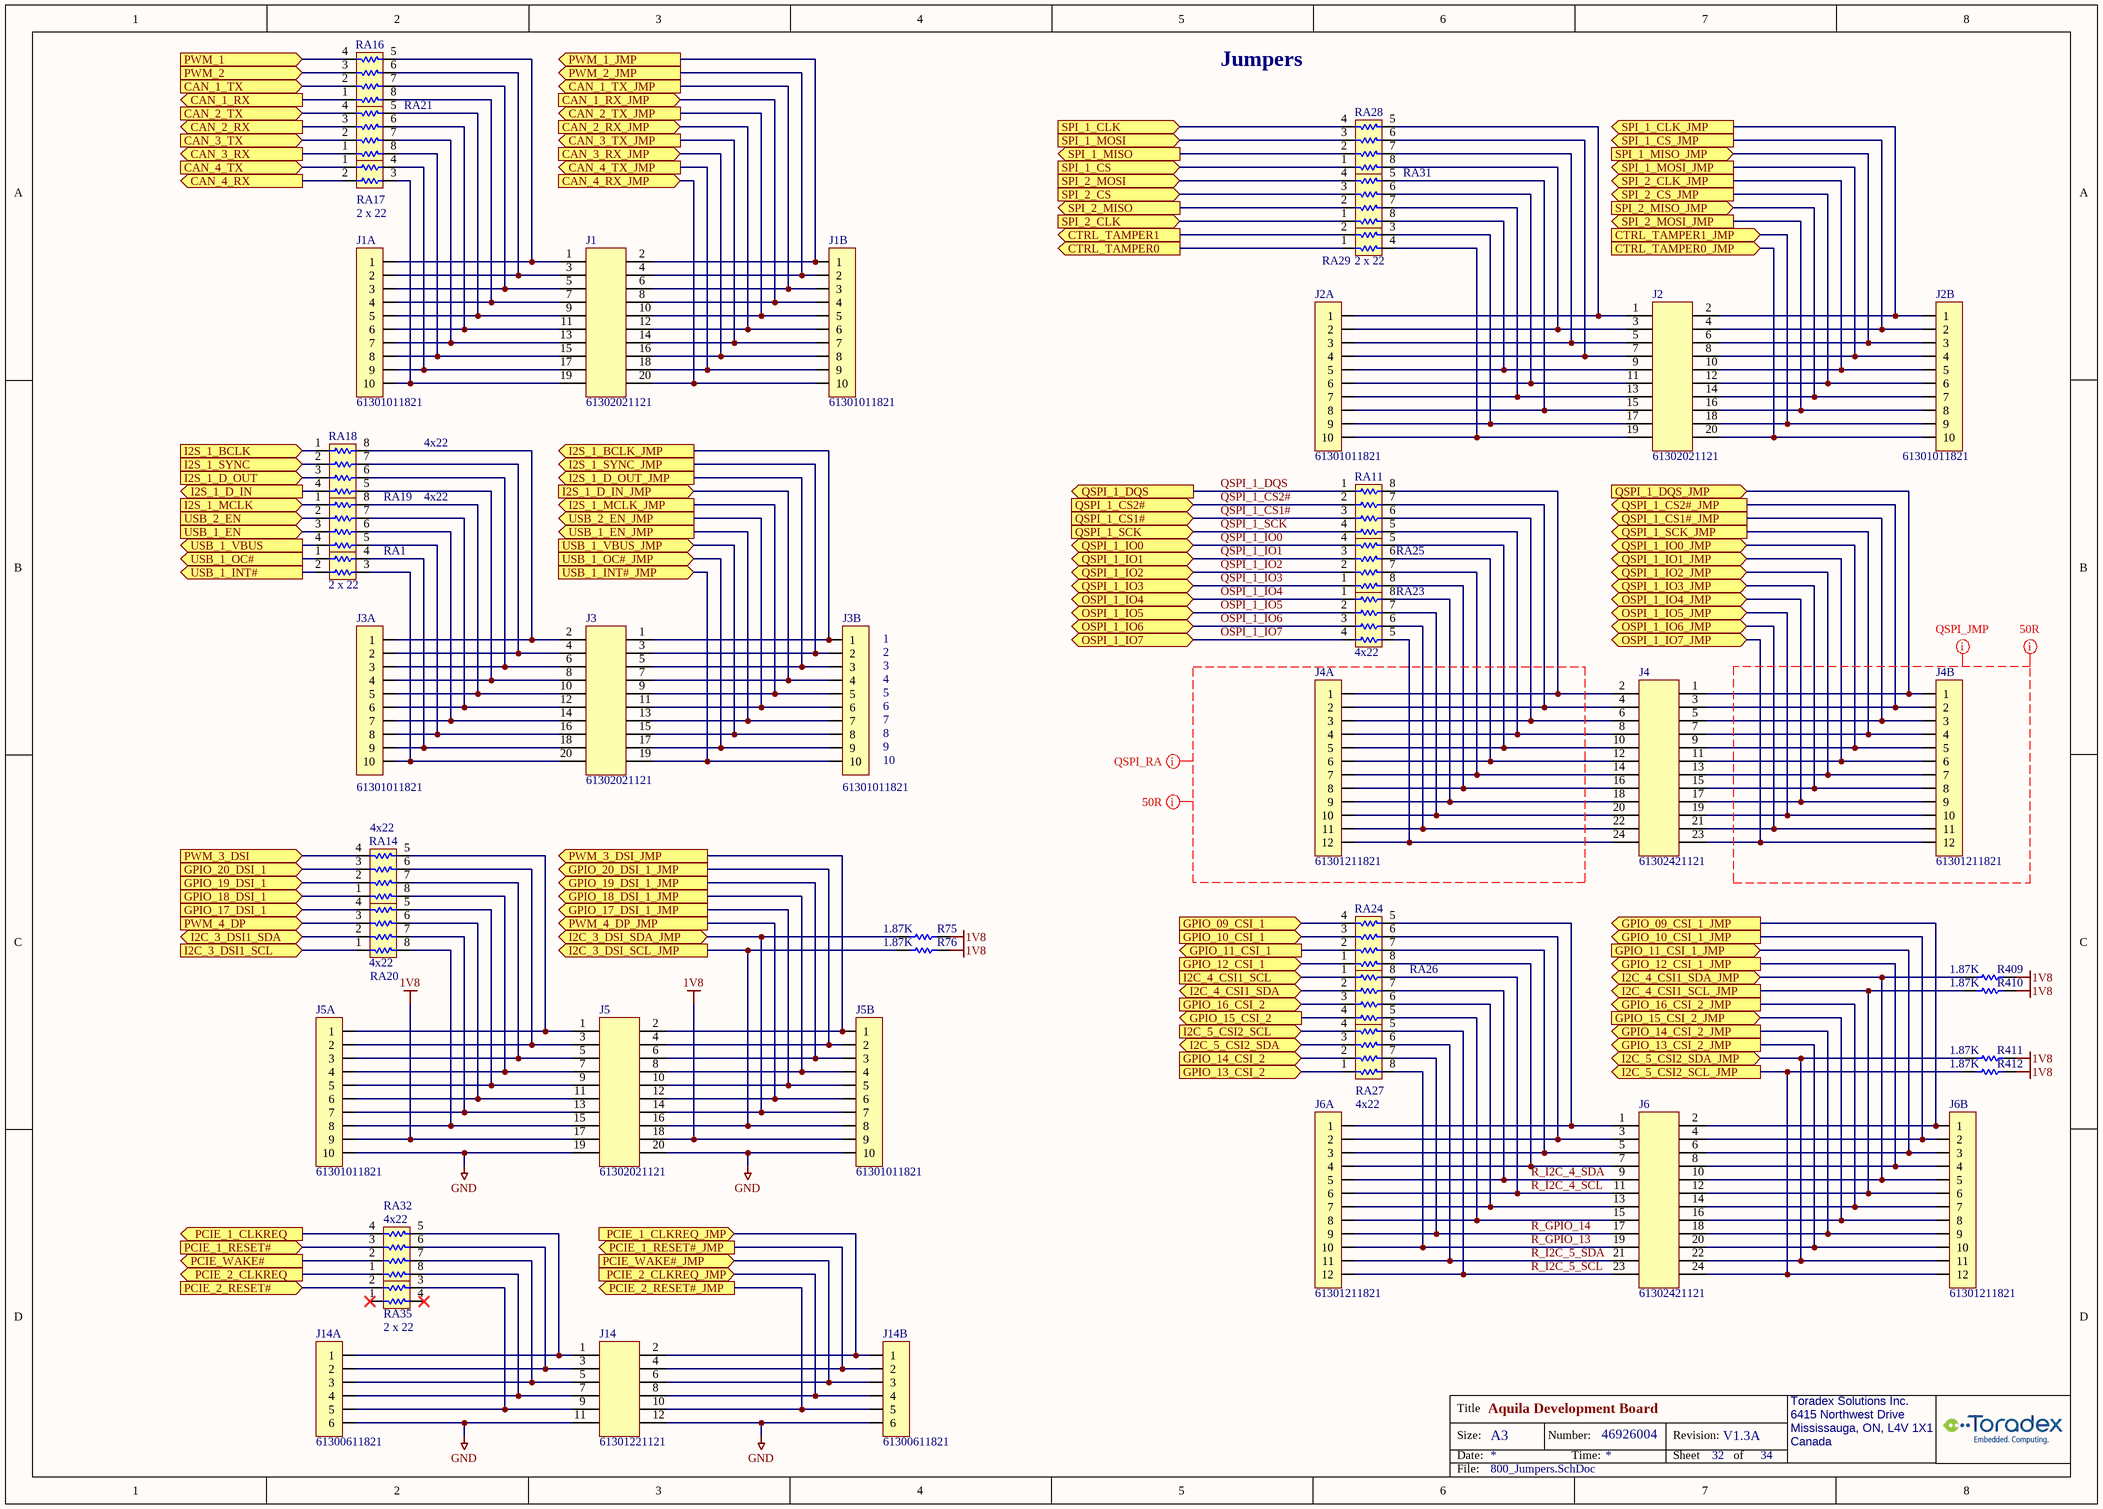
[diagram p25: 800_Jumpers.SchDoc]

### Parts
J1  61302021121  [WURTH_61302021121]
J1A  61301011821  [WURTH_61301011821]
J1B  61301011821  [WURTH_61301011821]
J2  61302021121  [WURTH_61302021121]
J2A  61301011821  [WURTH_61301011821]
J2B  61301011821  [WURTH_61301011821]
J3  61302021121  [WURTH_61302021121]
J3A  61301011821  [WURTH_61301011821]
J3B  61301011821  [WURTH_61301011821]
J4  61302421121  [WURTH_61302421121]
J4A  61301211821  [WURTH_61301211821]
J4B  61301211821  [WURTH_61301211821]
J5  61302021121  [WURTH_61302021121]
J5A  61301011821  [WURTH_61301011821]
J5B  61301011821  [WURTH_61301011821]
J6  61302421121  [WURTH_61302421121]
J6A  61301211821  [WURTH_61301211821]
J6B  61301211821  [WURTH_61301211821]
J14  61301221121  [WURTH_61301221121]
J14A  61300611821  [WURTH_61300611821]
J14B  61300611821  [WURTH_61300611821]
R75  value 1.87K  [R0402_RESC1005L]  (hidden comment: 1536-Res-0402-1.87K)
R76  value 1.87K  [R0402_RESC1005L]  (hidden comment: 1536-Res-0402-1.87K)
R409  value 1.87K  [R0402_RESC1005L]  (hidden comment: 1536-Res-0402-1.87K)
R410  value 1.87K  [R0402_RESC1005L]  (hidden comment: 1536-Res-0402-1.87K)
R411  value 1.87K  [R0402_RESC1005L]  (hidden comment: 1536-Res-0402-1.87K)
R412  value 1.87K  [R0402_RESC1005L]  (hidden comment: 1536-Res-0402-1.87K)
RA1  value 2 x 22  [EXB34V]  (hidden comment: 1265-ResArr-22ohm)
RA11  1848-ResArr-0804-22ohm  [RES_4_x_0804]  (value not drawn)
RA14  value 4x22  [RES_4_x_0804]  (hidden comment: 1848-ResArr-0804-22ohm)
RA16  value 4x22  [RES_4_x_0804]  (hidden comment: 1848-ResArr-0804-22ohm)
RA17  value 2 x 22  [EXB34V]  (hidden comment: 1265-ResArr-22ohm)
RA18  value 4x22  [RES_4_x_0804]  (hidden comment: 1848-ResArr-0804-22ohm)
RA19  value 4x22  [RES_4_x_0804]  (hidden comment: 1848-ResArr-0804-22ohm)
RA20  value 4x22  [RES_4_x_0804]  (hidden comment: 1848-ResArr-0804-22ohm)
RA21  value 4x22  [RES_4_x_0804]  (hidden comment: 1848-ResArr-0804-22ohm)
RA23  value 4x22  [RES_4_x_0804]  (hidden comment: 1848-ResArr-0804-22ohm)
RA24  value 4x22  [RES_4_x_0804]  (hidden comment: 1848-ResArr-0804-22ohm)
RA25  value 4x22  [RES_4_x_0804]  (hidden comment: 1848-ResArr-0804-22ohm)
RA26  value 4x22  [RES_4_x_0804]  (hidden comment: 1848-ResArr-0804-22ohm)
RA27  value 4x22  [RES_4_x_0804]  (hidden comment: 1848-ResArr-0804-22ohm)
RA28  value 4x22  [RES_4_x_0804]  (hidden comment: 1848-ResArr-0804-22ohm)
RA29  value 2 x 22  [EXB34V]  (hidden comment: 1265-ResArr-22ohm)
RA31  value 4x22  [RES_4_x_0804]  (hidden comment: 1848-ResArr-0804-22ohm)
RA32  value 4x22  [RES_4_x_0804]  (hidden comment: 1848-ResArr-0804-22ohm)
RA35  value 2 x 22  [EXB34V]  (hidden comment: 1265-ResArr-22ohm)

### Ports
CAN_1_RX (out), CAN_1_RX_JMP (in), CAN_1_TX (in), CAN_1_TX_JMP (out), CAN_2_RX (out), CAN_2_RX_JMP (in), CAN_2_TX (in), CAN_2_TX_JMP (out), CAN_3_RX (out), CAN_3_RX_JMP (in), CAN_3_TX (in), CAN_3_TX_JMP (out), CAN_4_RX (out), CAN_4_RX_JMP (in), CAN_4_TX (in), CAN_4_TX_JMP (out), CTRL_TAMPER0 (out), CTRL_TAMPER0_JMP (in), CTRL_TAMPER1 (out), CTRL_TAMPER1_JMP (in), GPIO_09_CSI_1 (in), GPIO_09_CSI_1_JMP (out), GPIO_10_CSI_1 (in), GPIO_10_CSI_1_JMP (out), GPIO_11_CSI_1 (out), GPIO_11_CSI_1_JMP (in), GPIO_12_CSI_1 (in), GPIO_12_CSI_1_JMP (out), GPIO_13_CSI_2 (in), GPIO_13_CSI_2_JMP (out), GPIO_14_CSI_2 (in), GPIO_14_CSI_2_JMP (out), GPIO_15_CSI_2 (out), GPIO_15_CSI_2_JMP (in), GPIO_16_CSI_2 (in), GPIO_16_CSI_2_JMP (out), GPIO_17_DSI_1 (in), GPIO_17_DSI_1_JMP (out), GPIO_18_DSI_1 (in), GPIO_18_DSI_1_JMP (out), GPIO_19_DSI_1 (in), GPIO_19_DSI_1_JMP (out), GPIO_20_DSI_1 (in), GPIO_20_DSI_1_JMP (out), I2C_3_DSI1_SCL (in), I2C_3_DSI1_SDA (bidir), I2C_3_DSI_SCL_JMP (out), I2C_3_DSI_SDA_JMP (bidir), I2C_4_CSI1_SCL (in), I2C_4_CSI1_SCL_JMP (out), I2C_4_CSI1_SDA (bidir), I2C_4_CSI1_SDA_JMP (bidir), I2C_5_CSI2_SCL (in), I2C_5_CSI2_SCL_JMP (out), I2C_5_CSI2_SDA (bidir), I2C_5_CSI2_SDA_JMP (bidir), I2S_1_BCLK (in), I2S_1_BCLK_JMP (out), I2S_1_D_IN (out), I2S_1_D_IN_JMP (in), I2S_1_D_OUT (in), I2S_1_D_OUT_JMP (out), I2S_1_MCLK (in), I2S_1_MCLK_JMP (out), I2S_1_SYNC (in), I2S_1_SYNC_JMP (out), OSPI_1_IO4 (bidir), OSPI_1_IO4_JMP (bidir), OSPI_1_IO5 (bidir), OSPI_1_IO5_JMP (bidir), OSPI_1_IO6 (bidir), OSPI_1_IO6_JMP (bidir), OSPI_1_IO7 (bidir), OSPI_1_IO7_JMP (bidir), PCIE_1_CLKREQ (out), PCIE_1_CLKREQ_JMP (in), PCIE_1_RESET# (in), PCIE_1_RESET#_JMP (out), PCIE_2_CLKREQ (out), PCIE_2_CLKREQ_JMP (in), PCIE_2_RESET# (in), PCIE_2_RESET#_JMP (out), PCIE_WAKE# (out), PCIE_WAKE#_JMP (in), PWM_1 (in), PWM_1_JMP (out), PWM_2 (in), PWM_2_JMP (out), PWM_3_DSI (in), PWM_3_DSI_JMP (out), PWM_4_DP (in), PWM_4_DP_JMP (out), QSPI_1_CS1# (in), QSPI_1_CS1#_JMP (out), QSPI_1_CS2# (in), QSPI_1_CS2#_JMP (out), QSPI_1_DQS (out), QSPI_1_DQS_JMP (in), QSPI_1_IO0 (bidir), QSPI_1_IO0_JMP (bidir), QSPI_1_IO1 (bidir), QSPI_1_IO1_JMP (bidir), QSPI_1_IO2 (bidir), QSPI_1_IO2_JMP (bidir), QSPI_1_IO3 (bidir), QSPI_1_IO3_JMP (bidir), QSPI_1_SCK (in), QSPI_1_SCK_JMP (out), SPI_1_CLK (in), SPI_1_CLK_JMP (out), SPI_1_CS (in), SPI_1_CS_JMP (out), SPI_1_MISO (out), SPI_1_MISO_JMP (in), SPI_1_MOSI (in), SPI_1_MOSI_JMP (out), SPI_2_CLK (in), SPI_2_CLK_JMP (out), SPI_2_CS (in), SPI_2_CS_JMP (out), SPI_2_MISO (out), SPI_2_MISO_JMP (in), SPI_2_MOSI (in), SPI_2_MOSI_JMP (out), USB_1_EN (in), USB_1_EN_JMP (out), USB_1_INT# (out), USB_1_INT#_JMP (in), USB_1_OC# (out), USB_1_OC#_JMP (in), USB_1_VBUS (out), USB_1_VBUS_JMP (in), USB_2_EN (in), USB_2_EN_JMP (out)

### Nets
1V8: J5.17 J5.18 J5A.9 J5B.9 R75.1 R76.1 R409.2 R410.2 R411.2 R412.2
GND: J5.19 J5.20 J5A.10 J5B.10 J14.11 J14.12 J14A.6 J14B.6
CAN_1_RX: RA16.1 ; port CAN_1_RX
CAN_1_RX_JMP: J1.8 J1B.4 ; port CAN_1_RX_JMP
CAN_1_TX: RA16.2 ; port CAN_1_TX
CAN_1_TX_JMP: J1.6 J1B.3 ; port CAN_1_TX_JMP
CAN_2_RX: RA21.3 ; port CAN_2_RX
CAN_2_RX_JMP: J1.12 J1B.6 ; port CAN_2_RX_JMP
CAN_2_TX: RA21.4 ; port CAN_2_TX
CAN_2_TX_JMP: J1.10 J1B.5 ; port CAN_2_TX_JMP
CAN_3_RX: RA21.1 ; port CAN_3_RX
CAN_3_RX_JMP: J1.16 J1B.8 ; port CAN_3_RX_JMP
CAN_3_TX: RA21.2 ; port CAN_3_TX
CAN_3_TX_JMP: J1.14 J1B.7 ; port CAN_3_TX_JMP
CAN_4_RX: RA17.2 ; port CAN_4_RX
CAN_4_RX_JMP: J1.20 J1B.10 ; port CAN_4_RX_JMP
CAN_4_TX: RA17.1 ; port CAN_4_TX
CAN_4_TX_JMP: J1.18 J1B.9 ; port CAN_4_TX_JMP
CTRL_TAMPER0: RA29.1 ; port CTRL_TAMPER0
CTRL_TAMPER0_JMP: J2.20 J2B.10 ; port CTRL_TAMPER0_JMP
CTRL_TAMPER1: RA29.2 ; port CTRL_TAMPER1
CTRL_TAMPER1_JMP: J2.18 J2B.9 ; port CTRL_TAMPER1_JMP
GPIO_09_CSI_1: RA24.4 ; port GPIO_09_CSI_1
GPIO_09_CSI_1_JMP: J6.2 J6B.1 ; port GPIO_09_CSI_1_JMP
GPIO_10_CSI_1: RA24.3 ; port GPIO_10_CSI_1
GPIO_10_CSI_1_JMP: J6.4 J6B.2 ; port GPIO_10_CSI_1_JMP
GPIO_11_CSI_1: RA24.2 ; port GPIO_11_CSI_1
GPIO_11_CSI_1_JMP: J6.6 J6B.3 ; port GPIO_11_CSI_1_JMP
GPIO_12_CSI_1: RA24.1 ; port GPIO_12_CSI_1
GPIO_12_CSI_1_JMP: J6.8 J6B.4 ; port GPIO_12_CSI_1_JMP
GPIO_13_CSI_2: RA27.1 ; port GPIO_13_CSI_2
GPIO_13_CSI_2_JMP: J6.20 J6B.10 ; port GPIO_13_CSI_2_JMP
GPIO_14_CSI_2: RA27.2 ; port GPIO_14_CSI_2
GPIO_14_CSI_2_JMP: J6.18 J6B.9 ; port GPIO_14_CSI_2_JMP
GPIO_15_CSI_2: RA26.4 ; port GPIO_15_CSI_2
GPIO_15_CSI_2_JMP: J6.16 J6B.8 ; port GPIO_15_CSI_2_JMP
GPIO_16_CSI_2: RA26.3 ; port GPIO_16_CSI_2
GPIO_16_CSI_2_JMP: J6.14 J6B.7 ; port GPIO_16_CSI_2_JMP
GPIO_17_DSI_1: RA20.4 ; port GPIO_17_DSI_1
GPIO_17_DSI_1_JMP: J5.10 J5B.5 ; port GPIO_17_DSI_1_JMP
GPIO_18_DSI_1: RA14.1 ; port GPIO_18_DSI_1
GPIO_18_DSI_1_JMP: J5.8 J5B.4 ; port GPIO_18_DSI_1_JMP
GPIO_19_DSI_1: RA14.2 ; port GPIO_19_DSI_1
GPIO_19_DSI_1_JMP: J5.6 J5B.3 ; port GPIO_19_DSI_1_JMP
GPIO_20_DSI_1: RA14.3 ; port GPIO_20_DSI_1
GPIO_20_DSI_1_JMP: J5.4 J5B.2 ; port GPIO_20_DSI_1_JMP
I2C_3_DSI1_SCL: RA20.1 ; port I2C_3_DSI1_SCL
I2C_3_DSI1_SDA: RA20.2 ; port I2C_3_DSI1_SDA
I2C_3_DSI_SCL_JMP: J5.16 J5B.8 R76.2 ; port I2C_3_DSI_SCL_JMP
I2C_3_DSI_SDA_JMP: J5.14 J5B.7 R75.2 ; port I2C_3_DSI_SDA_JMP
I2C_4_CSI1_SCL: RA26.1 ; port I2C_4_CSI1_SCL
I2C_4_CSI1_SCL_JMP: J6.12 J6B.6 R410.1 ; port I2C_4_CSI1_SCL_JMP
I2C_4_CSI1_SDA: RA26.2 ; port I2C_4_CSI1_SDA
I2C_4_CSI1_SDA_JMP: J6.10 J6B.5 R409.1 ; port I2C_4_CSI1_SDA_JMP
I2C_5_CSI2_SCL: RA27.4 ; port I2C_5_CSI2_SCL
I2C_5_CSI2_SCL_JMP: J6.24 J6B.12 R412.1 ; port I2C_5_CSI2_SCL_JMP
I2C_5_CSI2_SDA: RA27.3 ; port I2C_5_CSI2_SDA
I2C_5_CSI2_SDA_JMP: J6.22 J6B.11 R411.1 ; port I2C_5_CSI2_SDA_JMP
I2S_1_BCLK: RA18.1 ; port I2S_1_BCLK
I2S_1_BCLK_JMP: J3.1 J3B.1 ; port I2S_1_BCLK_JMP
I2S_1_D_IN: RA18.4 ; port I2S_1_D_IN
I2S_1_D_IN_JMP: J3.7 J3B.4 ; port I2S_1_D_IN_JMP
I2S_1_D_OUT: RA18.3 ; port I2S_1_D_OUT
I2S_1_D_OUT_JMP: J3.5 J3B.3 ; port I2S_1_D_OUT_JMP
I2S_1_MCLK: RA19.1 ; port I2S_1_MCLK
I2S_1_MCLK_JMP: J3.9 J3B.5 ; port I2S_1_MCLK_JMP
I2S_1_SYNC: RA18.2 ; port I2S_1_SYNC
I2S_1_SYNC_JMP: J3.3 J3B.2 ; port I2S_1_SYNC_JMP
OSPI_1_IO4: RA23.1 ; port OSPI_1_IO4
OSPI_1_IO4_JMP: J4.17 J4B.9 ; port OSPI_1_IO4_JMP
OSPI_1_IO5: RA23.2 ; port OSPI_1_IO5
OSPI_1_IO5_JMP: J4.19 J4B.10 ; port OSPI_1_IO5_JMP
OSPI_1_IO6: RA23.3 ; port OSPI_1_IO6
OSPI_1_IO6_JMP: J4.21 J4B.11 ; port OSPI_1_IO6_JMP
OSPI_1_IO7: RA23.4 ; port OSPI_1_IO7
OSPI_1_IO7_JMP: J4.23 J4B.12 ; port OSPI_1_IO7_JMP
PCIE_1_CLKREQ: RA32.4 ; port PCIE_1_CLKREQ
PCIE_1_CLKREQ_JMP: J14.2 J14B.1 ; port PCIE_1_CLKREQ_JMP
PCIE_1_RESET#: RA32.3 ; port PCIE_1_RESET#
PCIE_1_RESET#_JMP: J14.4 J14B.2 ; port PCIE_1_RESET#_JMP
PCIE_2_CLKREQ: RA32.1 ; port PCIE_2_CLKREQ
PCIE_2_CLKREQ_JMP: J14.8 J14B.4 ; port PCIE_2_CLKREQ_JMP
PCIE_2_RESET#: RA35.2 ; port PCIE_2_RESET#
PCIE_2_RESET#_JMP: J14.10 J14B.5 ; port PCIE_2_RESET#_JMP
PCIE_WAKE#: RA32.2 ; port PCIE_WAKE#
PCIE_WAKE#_JMP: J14.6 J14B.3 ; port PCIE_WAKE#_JMP
PWM_1: RA16.4 ; port PWM_1
PWM_1_JMP: J1.2 J1B.1 ; port PWM_1_JMP
PWM_2: RA16.3 ; port PWM_2
PWM_2_JMP: J1.4 J1B.2 ; port PWM_2_JMP
PWM_3_DSI: RA14.4 ; port PWM_3_DSI
PWM_3_DSI_JMP: J5.2 J5B.1 ; port PWM_3_DSI_JMP
PWM_4_DP: RA20.3 ; port PWM_4_DP
PWM_4_DP_JMP: J5.12 J5B.6 ; port PWM_4_DP_JMP
QSPI_1_CS1#: RA11.3 ; port QSPI_1_CS1#
QSPI_1_CS1#_JMP: J4.5 J4B.3 ; port QSPI_1_CS1#_JMP
QSPI_1_CS2#: RA11.2 ; port QSPI_1_CS2#
QSPI_1_CS2#_JMP: J4.3 J4B.2 ; port QSPI_1_CS2#_JMP
QSPI_1_DQS: RA11.1 ; port QSPI_1_DQS
QSPI_1_DQS_JMP: J4.1 J4B.1 ; port QSPI_1_DQS_JMP
QSPI_1_IO0: RA25.4 ; port QSPI_1_IO0
QSPI_1_IO0_JMP: J4.9 J4B.5 ; port QSPI_1_IO0_JMP
QSPI_1_IO1: RA25.3 ; port QSPI_1_IO1
QSPI_1_IO1_JMP: J4.11 J4B.6 ; port QSPI_1_IO1_JMP
QSPI_1_IO2: RA25.2 ; port QSPI_1_IO2
QSPI_1_IO2_JMP: J4.13 J4B.7 ; port QSPI_1_IO2_JMP
QSPI_1_IO3: RA25.1 ; port QSPI_1_IO3
QSPI_1_IO3_JMP: J4.15 J4B.8 ; port QSPI_1_IO3_JMP
QSPI_1_SCK: RA11.4 ; port QSPI_1_SCK
QSPI_1_SCK_JMP: J4.7 J4B.4 ; port QSPI_1_SCK_JMP
R_GPIO_13: J6.19 J6A.10 RA27.8
R_GPIO_14: J6.17 J6A.9 RA27.7
R_I2C_4_SCL: J6.11 J6A.6 RA26.8
R_I2C_4_SDA: J6.9 J6A.5 RA26.7
R_I2C_5_SCL: J6.23 J6A.12 RA27.5
R_I2C_5_SDA: J6.21 J6A.11 RA27.6
SPI_1_CLK: RA28.4 ; port SPI_1_CLK
SPI_1_CLK_JMP: J2.2 J2B.1 ; port SPI_1_CLK_JMP
SPI_1_CS: RA28.1 ; port SPI_1_CS
SPI_1_CS_JMP: J2.4 J2B.2 ; port SPI_1_CS_JMP
SPI_1_MISO: RA28.2 ; port SPI_1_MISO
SPI_1_MISO_JMP: J2.6 J2B.3 ; port SPI_1_MISO_JMP
SPI_1_MOSI: RA28.3 ; port SPI_1_MOSI
SPI_1_MOSI_JMP: J2.8 J2B.4 ; port SPI_1_MOSI_JMP
SPI_2_CLK: RA31.1 ; port SPI_2_CLK
SPI_2_CLK_JMP: J2.10 J2B.5 ; port SPI_2_CLK_JMP
SPI_2_CS: RA31.3 ; port SPI_2_CS
SPI_2_CS_JMP: J2.12 J2B.6 ; port SPI_2_CS_JMP
SPI_2_MISO: RA31.2 ; port SPI_2_MISO
SPI_2_MISO_JMP: J2.14 J2B.7 ; port SPI_2_MISO_JMP
SPI_2_MOSI: RA31.4 ; port SPI_2_MOSI
SPI_2_MOSI_JMP: J2.16 J2B.8 ; port SPI_2_MOSI_JMP
USB_1_EN: RA19.3 ; port USB_1_EN
USB_1_EN_JMP: J3.13 J3B.7 ; port USB_1_EN_JMP
USB_1_INT#: RA1.2 ; port USB_1_INT#
USB_1_INT#_JMP: J3.19 J3B.10 ; port USB_1_INT#_JMP
USB_1_OC#: RA1.1 ; port USB_1_OC#
USB_1_OC#_JMP: J3.17 J3B.9 ; port USB_1_OC#_JMP
USB_1_VBUS: RA19.4 ; port USB_1_VBUS
USB_1_VBUS_JMP: J3.15 J3B.8 ; port USB_1_VBUS_JMP
USB_2_EN: RA19.2 ; port USB_2_EN
USB_2_EN_JMP: J3.11 J3B.6 ; port USB_2_EN_JMP
NetJ1_1: J1.1 J1A.1 RA16.5
NetJ1_3: J1.3 J1A.2 RA16.6
NetJ1_5: J1.5 J1A.3 RA16.7
NetJ1_7: J1.7 J1A.4 RA16.8
NetJ1_9: J1.9 J1A.5 RA21.5
NetJ1_11: J1.11 J1A.6 RA21.6
NetJ1_13: J1.13 J1A.7 RA21.7
NetJ1_15: J1.15 J1A.8 RA21.8
NetJ1_17: J1.17 J1A.9 RA17.4
NetJ1_19: J1.19 J1A.10 RA17.3
NetJ2_1: J2.1 J2A.1 RA28.5
NetJ2_3: J2.3 J2A.2 RA28.8
NetJ2_5: J2.5 J2A.3 RA28.7
NetJ2_7: J2.7 J2A.4 RA28.6
NetJ2_9: J2.9 J2A.5 RA31.8
NetJ2_11: J2.11 J2A.6 RA31.6
NetJ2_13: J2.13 J2A.7 RA31.7
NetJ2_15: J2.15 J2A.8 RA31.5
NetJ2_17: J2.17 J2A.9 RA29.3
NetJ2_19: J2.19 J2A.10 RA29.4
NetJ3_2: J3.2 J3A.1 RA18.8
NetJ3_4: J3.4 J3A.2 RA18.7
NetJ3_6: J3.6 J3A.3 RA18.6
NetJ3_8: J3.8 J3A.4 RA18.5
NetJ3_10: J3.10 J3A.5 RA19.8
NetJ3_12: J3.12 J3A.6 RA19.7
NetJ3_14: J3.14 J3A.7 RA19.6
NetJ3_16: J3.16 J3A.8 RA19.5
NetJ3_18: J3.18 J3A.9 RA1.4
NetJ3_20: J3.20 J3A.10 RA1.3
NetJ4_2: J4.2 J4A.1 RA11.8
NetJ4_4: J4.4 J4A.2 RA11.7
NetJ4_6: J4.6 J4A.3 RA11.6
NetJ4_8: J4.8 J4A.4 RA11.5
NetJ4_10: J4.10 J4A.5 RA25.5
NetJ4_12: J4.12 J4A.6 RA25.6
NetJ4_14: J4.14 J4A.7 RA25.7
NetJ4_16: J4.16 J4A.8 RA25.8
NetJ4_18: J4.18 J4A.9 RA23.8
NetJ4_20: J4.20 J4A.10 RA23.7
NetJ4_22: J4.22 J4A.11 RA23.6
NetJ4_24: J4.24 J4A.12 RA23.5
NetJ5_1: J5.1 J5A.1 RA14.5
NetJ5_3: J5.3 J5A.2 RA14.6
NetJ5_5: J5.5 J5A.3 RA14.7
NetJ5_7: J5.7 J5A.4 RA14.8
NetJ5_9: J5.9 J5A.5 RA20.5
NetJ5_11: J5.11 J5A.6 RA20.6
NetJ5_13: J5.13 J5A.7 RA20.7
NetJ5_15: J5.15 J5A.8 RA20.8
NetJ6_1: J6.1 J6A.1 RA24.5
NetJ6_3: J6.3 J6A.2 RA24.6
NetJ6_5: J6.5 J6A.3 RA24.7
NetJ6_7: J6.7 J6A.4 RA24.8
NetJ6_13: J6.13 J6A.7 RA26.6
NetJ6_15: J6.15 J6A.8 RA26.5
NetJ14_1: J14.1 J14A.1 RA32.5
NetJ14_3: J14.3 J14A.2 RA32.6
NetJ14_5: J14.5 J14A.3 RA32.7
NetJ14_7: J14.7 J14A.4 RA32.8
NetJ14_9: J14.9 J14A.5 RA35.3

Not connected (* = marked no-connect by the designer): RA35 1* 4*

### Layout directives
net class 50R: (no net found under the mark)
net class QSPI_RA: (no net found under the mark)
net class QSPI_JMP: (no net found under the mark)

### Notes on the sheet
- Jumpers
- (near J3B) 1
- (near J3B) 2
- (near J3B) 3
- (near J3B) 4
- (near J3B) 5
- (near J3B) 6
- (near J3B) 7
- (near J3B) 8
- (near J3B) 9
- (near J3B) 10

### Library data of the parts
J1-J3 J5 = 2203-Conn-Hdr 2x10 2.54MM: (-40 to 105 DegC) CONN HEADER MALE VERT 2x10 20POS 2.54MM TH; Mfr: Wurth Electronics; PN: 2203
J1A J1B J2A J2B J3A J3B J5A J5B = 2202-Conn-Hdr 1x10 2.54MM F: as J60 on sheet 215_Translators2
J4 J6 = 2206-Conn-Hdr 2x12 2.54MM: (-40 to 105 DegC) CONN HEADER MALE VERT 2x12 24POS 2.54MM TH; Mfr: Wurth Electronics; PN: 2206
J4A J4B J6A J6B = 2221-Conn-Hdr 1x12 2.54MM F: (-40 to 105 DegC) CONN HEADER FEMALE VERT 1x12 12POS 2.54MM TH; Mfr: Wurth Electronics; PN: 2221
J14 = 2266-Conn-Hdr 2x6 2.54MM: (-40 to 105 DegC) CONN HEADER MALE VERT 2x6 12POS 2.54MM TH; Mfr: Wurth Electronics; PN: 2266
J14A J14B = 2189-Conn-Hdr 1x6 2.54MM F: (-40 to 125 DegC) CONN HEADER FEMALE 1x6 6POS  2.54MM TH; Mfr: Wurth Electronics; PN: 2189
R75 R76 = 1536-Res-0402-1.87K: (-55 to 155 DegC AEC) RES 1.87K OHM 1% 1/16W 100ppm 0402; MfrNo: RMCF0402FT1K87; Mfr: Stackpole Electronics; PN: 1536; Alt: AC0402FR-071K87L,RK73H1ETTP1871F,ERJ-2RKF1871X
R409-R412 = 1536-Res-0402-1.87K: as R88 on sheet 225_Debug2
RA1 RA17 RA29 RA35 = 1265-ResArr-22ohm: (-55 to 125 DegC) RES ARRAY 2 RES 22 OHM 5% 0606 200ppm; Mfr: Panasonic; MfrNo: EXB-34V220JV; PN: 1265; Alt: EXB-V4V220JV
RA11 = 1848-ResArr-0804-22ohm: (-55 to 125 DegC) RES ARRAY 4 RES 22 OHM 0804 +/-300ppm SMD; MfrNo: CAT10A-220J4LF; Mfr: Bourns; PN: 1848; Alt: PN1819; Value: 4x22
RA14 RA16 RA18-RA21 RA23-RA28 RA31 RA32 = 1848-ResArr-0804-22ohm: (-55 to 125 DegC) RES ARRAY 4 RES 22 OHM 0804 +/-300ppm SMD; MfrNo: CAT10A-220J4LF; Mfr: Bourns; PN: 1848; Alt: PN1819

## Sheet 810_Jumpers.SchDoc: Aquila Development Board
size A3; Organization: Toradex Solutions Inc.; Address1: 6415 Northwest Drive; Address2: Mississauga, ON, L4V 1X1; Address3: Canada; SheetNumber: 33; SheetTotal: 34
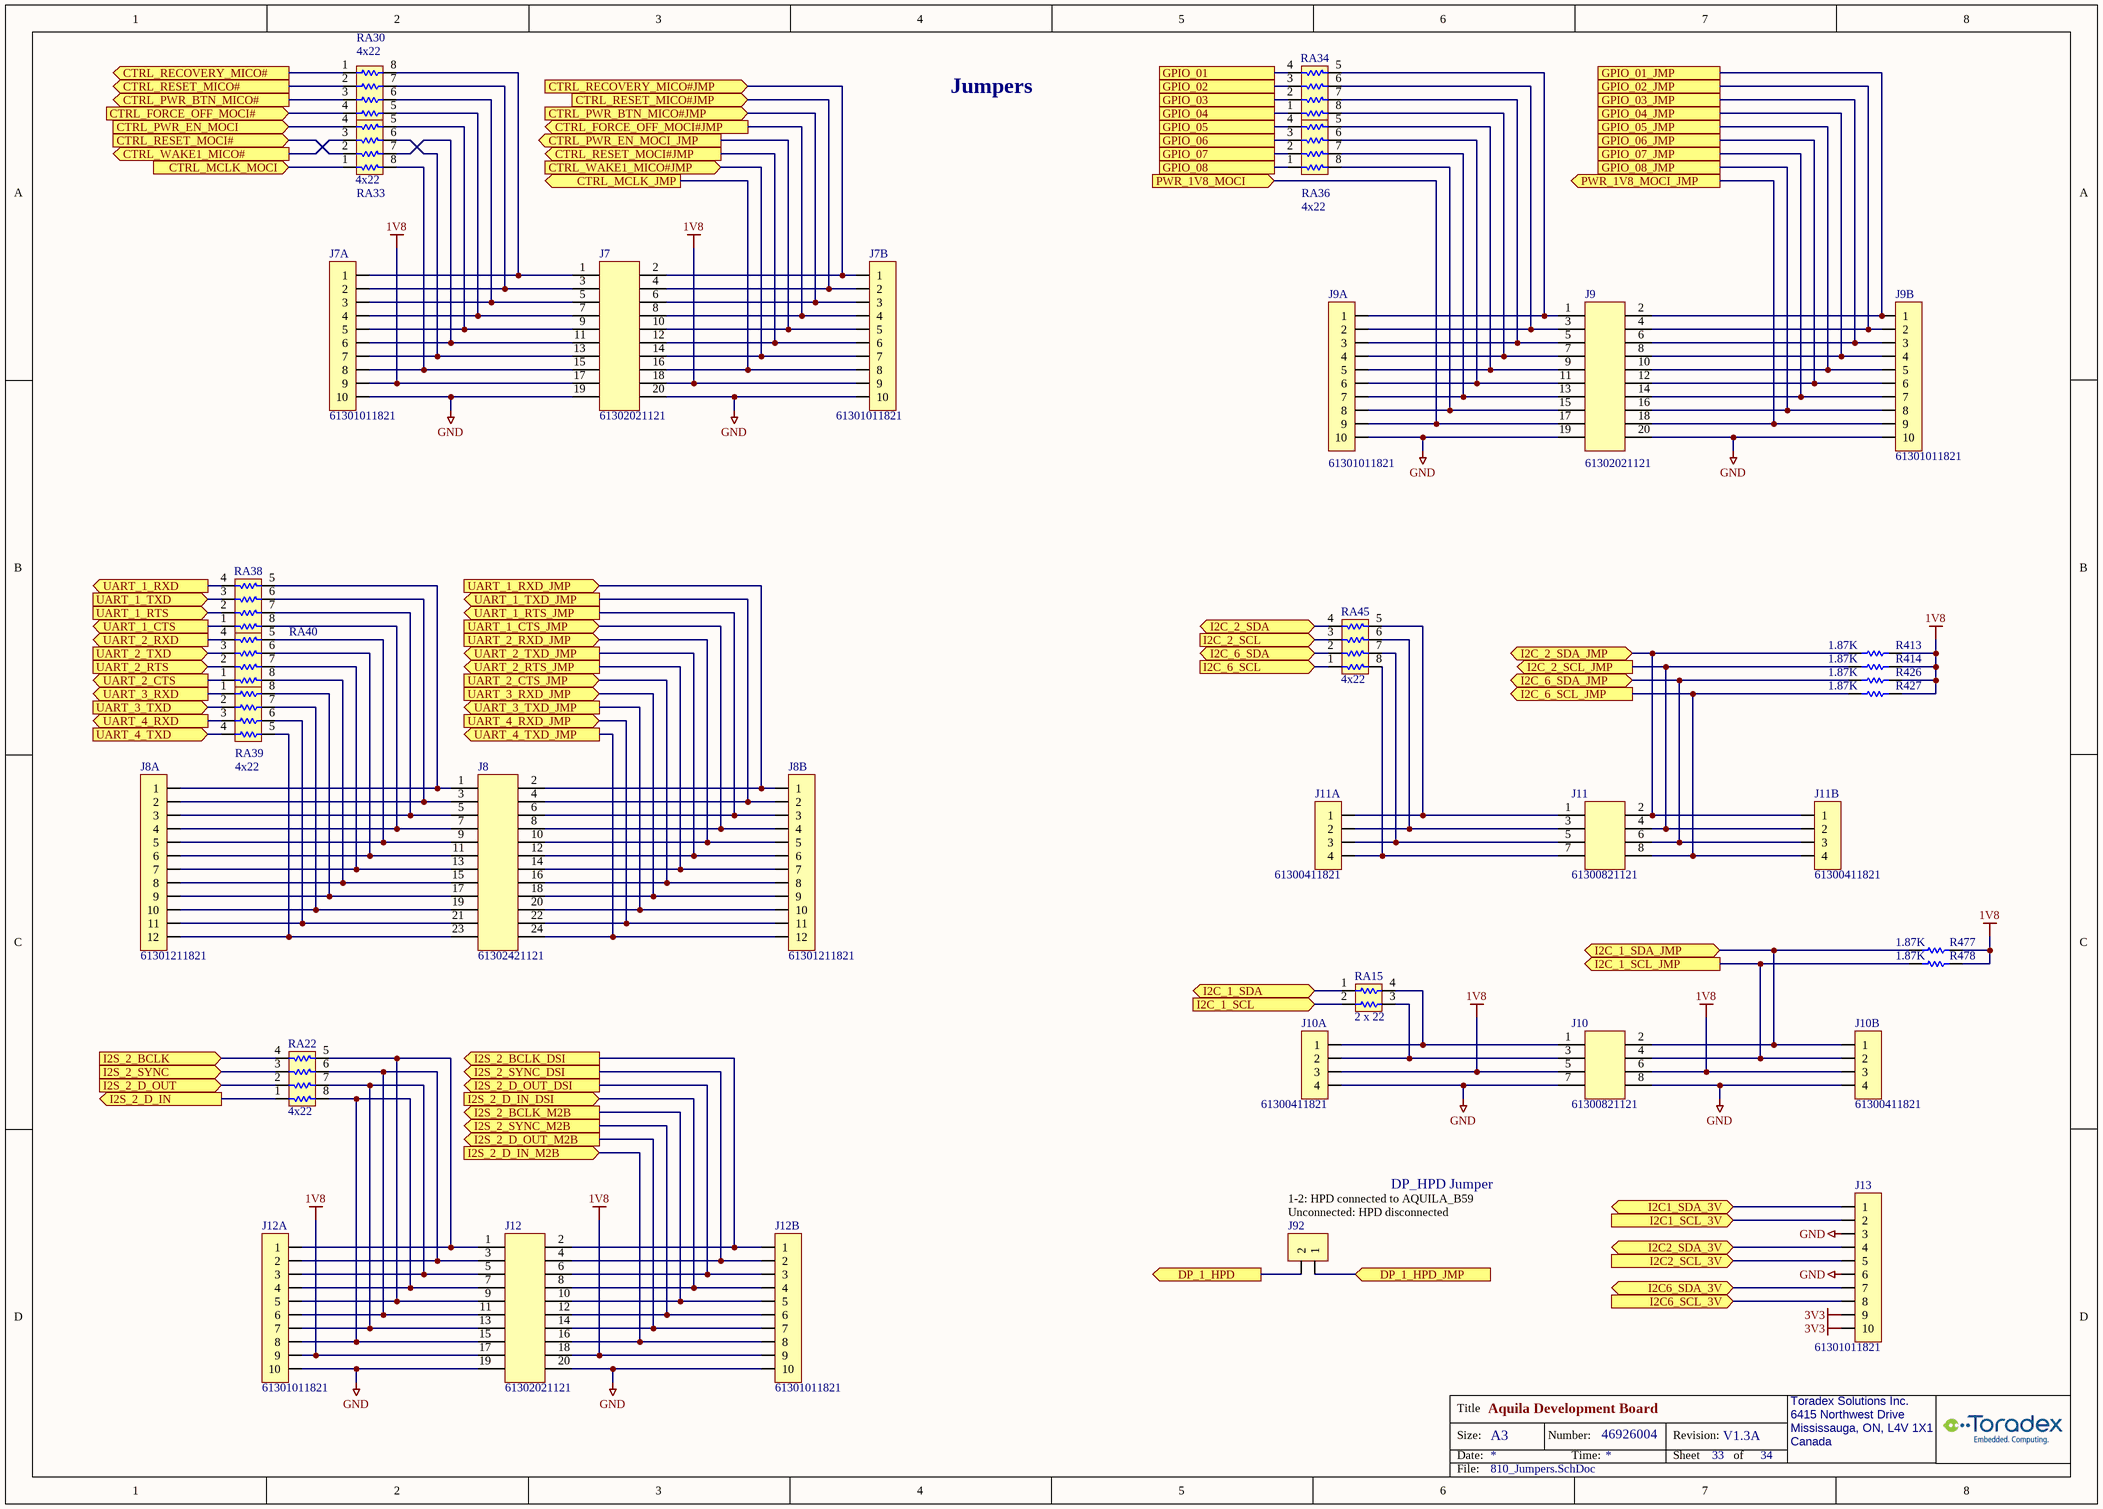
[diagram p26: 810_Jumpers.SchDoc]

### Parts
J7  61302021121  [WURTH_61302021121]
J7A  61301011821  [WURTH_61301011821]
J7B  61301011821  [WURTH_61301011821]
J8  61302421121  [WURTH_61302421121]
J8A  61301211821  [WURTH_61301211821]
J8B  61301211821  [WURTH_61301211821]
J9  61302021121  [WURTH_61302021121]
J9A  61301011821  [WURTH_61301011821]
J9B  61301011821  [WURTH_61301011821]
J10  61300821121  [WURTH_61300821121]
J10A  61300411821  [WURTH_61300411821]
J10B  61300411821  [WURTH_61300411821]
J11  61300821121  [WURTH_61300821121]
J11A  61300411821  [WURTH_61300411821]
J11B  61300411821  [WURTH_61300411821]
J12  61302021121  [WURTH_61302021121]
J12A  61301011821  [WURTH_61301011821]
J12B  61301011821  [WURTH_61301011821]
J13  61301011821  [WURTH_61301011821]
J92  67996-200HLF  [CON_HDR1X2]  (value not drawn)
R413  value 1.87K  [R0402_RESC1005L]  (hidden comment: 1536-Res-0402-1.87K)
R414  value 1.87K  [R0402_RESC1005L]  (hidden comment: 1536-Res-0402-1.87K)
R426  value 1.87K  [R0402_RESC1005L]  (hidden comment: 1536-Res-0402-1.87K)
R427  value 1.87K  [R0402_RESC1005L]  (hidden comment: 1536-Res-0402-1.87K)
R477  value 1.87K  [R0402_RESC1005L]  (hidden comment: 1536-Res-0402-1.87K)
R478  value 1.87K  [R0402_RESC1005L]  (hidden comment: 1536-Res-0402-1.87K)
RA15  value 2 x 22  [EXB34V]  (hidden comment: 1265-ResArr-22ohm)
RA22  value 4x22  [RES_4_x_0804]  (hidden comment: 1848-ResArr-0804-22ohm)
RA30  value 4x22  [RES_4_x_0804]  (hidden comment: 1848-ResArr-0804-22ohm)
RA33  value 4x22  [RES_4_x_0804]  (hidden comment: 1848-ResArr-0804-22ohm)
RA34  value 4x22  [RES_4_x_0804]  (hidden comment: 1848-ResArr-0804-22ohm)
RA36  value 4x22  [RES_4_x_0804]  (hidden comment: 1848-ResArr-0804-22ohm)
RA38  value 4x22  [RES_4_x_0804]  (hidden comment: 1848-ResArr-0804-22ohm)
RA39  value 4x22  [RES_4_x_0804]  (hidden comment: 1848-ResArr-0804-22ohm)
RA40  value 4x22  [RES_4_x_0804]  (hidden comment: 1848-ResArr-0804-22ohm)
RA45  value 4x22  [RES_4_x_0804]  (hidden comment: 1848-ResArr-0804-22ohm)

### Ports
CTRL_FORCE_OFF_MOCI# (in), CTRL_FORCE_OFF_MOCI#JMP (out), CTRL_MCLK_JMP (out), CTRL_MCLK_MOCI (in), CTRL_PWR_BTN_MICO# (out), CTRL_PWR_BTN_MICO#JMP (in), CTRL_PWR_EN_MOCI (in), CTRL_PWR_EN_MOCI_JMP (out), CTRL_RECOVERY_MICO# (out), CTRL_RECOVERY_MICO#JMP (in), CTRL_RESET_MICO# (out), CTRL_RESET_MICO#JMP (in), CTRL_RESET_MOCI# (in), CTRL_RESET_MOCI#JMP (out), CTRL_WAKE1_MICO# (out), CTRL_WAKE1_MICO#JMP (in), DP_1_HPD (out), DP_1_HPD_JMP (in), GPIO_01, GPIO_01_JMP, GPIO_02, GPIO_02_JMP, GPIO_03, GPIO_03_JMP, GPIO_04, GPIO_04_JMP, GPIO_05, GPIO_05_JMP, GPIO_06, GPIO_06_JMP, GPIO_07, GPIO_07_JMP, GPIO_08, GPIO_08_JMP, I2C1_SCL_3V (in), I2C1_SDA_3V (bidir), I2C2_SCL_3V (in), I2C2_SDA_3V (bidir), I2C6_SCL_3V (in), I2C6_SDA_3V (bidir), I2C_1_SCL (in), I2C_1_SCL_JMP (out), I2C_1_SDA (bidir), I2C_1_SDA_JMP (bidir), I2C_2_SCL (in), I2C_2_SCL_JMP (out), I2C_2_SDA (bidir), I2C_2_SDA_JMP (bidir), I2C_6_SCL (in), I2C_6_SCL_JMP (out), I2C_6_SDA (bidir), I2C_6_SDA_JMP (bidir), I2S_2_BCLK (in), I2S_2_BCLK_DSI (out), I2S_2_BCLK_M2B (out), I2S_2_D_IN (out), I2S_2_D_IN_DSI (in), I2S_2_D_IN_M2B (in), I2S_2_D_OUT (in), I2S_2_D_OUT_DSI (out), I2S_2_D_OUT_M2B (out), I2S_2_SYNC (in), I2S_2_SYNC_DSI (out), I2S_2_SYNC_M2B (out), PWR_1V8_MOCI (in), PWR_1V8_MOCI_JMP (out), UART_1_CTS (out), UART_1_CTS_JMP (in), UART_1_RTS (in), UART_1_RTS_JMP (out), UART_1_RXD (out), UART_1_RXD_JMP (in), UART_1_TXD (in), UART_1_TXD_JMP (out), UART_2_CTS (out), UART_2_CTS_JMP (in), UART_2_RTS (in), UART_2_RTS_JMP (out), UART_2_RXD (out), UART_2_RXD_JMP (in), UART_2_TXD (in), UART_2_TXD_JMP (out), UART_3_RXD (out), UART_3_RXD_JMP (in), UART_3_TXD (in), UART_3_TXD_JMP (out), UART_4_RXD (out), UART_4_RXD_JMP (in), UART_4_TXD (in), UART_4_TXD_JMP (out)

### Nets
1V8: J7.17 J7.18 J7A.9 J7B.9 J10.5 J10.6 J10A.3 J10B.3 J12.17 J12.18 J12A.9 J12B.9 R413.1 R414.1 R426.1 R427.1 R477.1 R478.1
3V3: J13.9 J13.10
GND: J7.19 J7.20 J7A.10 J7B.10 J9.19 J9.20 J9A.10 J9B.10 J10.7 J10.8 J10A.4 J10B.4 J12.19 J12.20 J12A.10 J12B.10 J13.3 J13.6
CTRL_FORCE_OFF_MOCI#: RA30.4 ; port CTRL_FORCE_OFF_MOCI#
CTRL_FORCE_OFF_MOCI#JMP: J7.8 J7B.4 ; port CTRL_FORCE_OFF_MOCI#JMP
CTRL_MCLK_JMP: J7.16 J7B.8 ; port CTRL_MCLK_JMP
CTRL_MCLK_MOCI: RA33.1 ; port CTRL_MCLK_MOCI
CTRL_PWR_BTN_MICO#: RA30.3 ; port CTRL_PWR_BTN_MICO#
CTRL_PWR_BTN_MICO#JMP: J7.6 J7B.3 ; port CTRL_PWR_BTN_MICO#JMP
CTRL_PWR_EN_MOCI: RA33.4 ; port CTRL_PWR_EN_MOCI
CTRL_PWR_EN_MOCI_JMP: J7.10 J7B.5 ; port CTRL_PWR_EN_MOCI_JMP
CTRL_RECOVERY_MICO#: RA30.1 ; port CTRL_RECOVERY_MICO#
CTRL_RECOVERY_MICO#JMP: J7.2 J7B.1 ; port CTRL_RECOVERY_MICO#JMP
CTRL_RESET_MICO#: RA30.2 ; port CTRL_RESET_MICO#
CTRL_RESET_MICO#JMP: J7.4 J7B.2 ; port CTRL_RESET_MICO#JMP
CTRL_RESET_MOCI#: RA33.2 ; port CTRL_RESET_MOCI#
CTRL_RESET_MOCI#JMP: J7.12 J7B.6 ; port CTRL_RESET_MOCI#JMP
CTRL_WAKE1_MICO#: RA33.3 ; port CTRL_WAKE1_MICO#
CTRL_WAKE1_MICO#JMP: J7.14 J7B.7 ; port CTRL_WAKE1_MICO#JMP
DP_1_HPD: J92.2 ; port DP_1_HPD
DP_1_HPD_JMP: J92.1 ; port DP_1_HPD_JMP
GPIO_01: RA34.4 ; port GPIO_01
GPIO_01_JMP: J9.2 J9B.1 ; port GPIO_01_JMP
GPIO_02: RA34.3 ; port GPIO_02
GPIO_02_JMP: J9.4 J9B.2 ; port GPIO_02_JMP
GPIO_03: RA34.2 ; port GPIO_03
GPIO_03_JMP: J9.6 J9B.3 ; port GPIO_03_JMP
GPIO_04: RA34.1 ; port GPIO_04
GPIO_04_JMP: J9.8 J9B.4 ; port GPIO_04_JMP
GPIO_05: RA36.4 ; port GPIO_05
GPIO_05_JMP: J9.10 J9B.5 ; port GPIO_05_JMP
GPIO_06: RA36.3 ; port GPIO_06
GPIO_06_JMP: J9.12 J9B.6 ; port GPIO_06_JMP
GPIO_07: RA36.2 ; port GPIO_07
GPIO_07_JMP: J9.14 J9B.7 ; port GPIO_07_JMP
GPIO_08: RA36.1 ; port GPIO_08
GPIO_08_JMP: J9.16 J9B.8 ; port GPIO_08_JMP
I2C1_SCL_3V: J13.2 ; port I2C1_SCL_3V
I2C1_SDA_3V: J13.1 ; port I2C1_SDA_3V
I2C2_SCL_3V: J13.5 ; port I2C2_SCL_3V
I2C2_SDA_3V: J13.4 ; port I2C2_SDA_3V
I2C6_SCL_3V: J13.8 ; port I2C6_SCL_3V
I2C6_SDA_3V: J13.7 ; port I2C6_SDA_3V
I2C_1_SCL: RA15.2 ; port I2C_1_SCL
I2C_1_SCL_JMP: J10.4 J10B.2 R478.2 ; port I2C_1_SCL_JMP
I2C_1_SDA: RA15.1 ; port I2C_1_SDA
I2C_1_SDA_JMP: J10.2 J10B.1 R477.2 ; port I2C_1_SDA_JMP
I2C_2_SCL: RA45.3 ; port I2C_2_SCL
I2C_2_SCL_JMP: J11.4 J11B.2 R414.2 ; port I2C_2_SCL_JMP
I2C_2_SDA: RA45.4 ; port I2C_2_SDA
I2C_2_SDA_JMP: J11.2 J11B.1 R413.2 ; port I2C_2_SDA_JMP
I2C_6_SCL: RA45.1 ; port I2C_6_SCL
I2C_6_SCL_JMP: J11.8 J11B.4 R427.2 ; port I2C_6_SCL_JMP
I2C_6_SDA: RA45.2 ; port I2C_6_SDA
I2C_6_SDA_JMP: J11.6 J11B.3 R426.2 ; port I2C_6_SDA_JMP
I2S_2_BCLK: RA22.4 ; port I2S_2_BCLK
I2S_2_BCLK_DSI: J12.2 J12B.1 ; port I2S_2_BCLK_DSI
I2S_2_BCLK_M2B: J12.10 J12B.5 ; port I2S_2_BCLK_M2B
I2S_2_D_IN: RA22.1 ; port I2S_2_D_IN
I2S_2_D_IN_DSI: J12.8 J12B.4 ; port I2S_2_D_IN_DSI
I2S_2_D_IN_M2B: J12.16 J12B.8 ; port I2S_2_D_IN_M2B
I2S_2_D_OUT: RA22.2 ; port I2S_2_D_OUT
I2S_2_D_OUT_DSI: J12.6 J12B.3 ; port I2S_2_D_OUT_DSI
I2S_2_D_OUT_M2B: J12.14 J12B.7 ; port I2S_2_D_OUT_M2B
I2S_2_SYNC: RA22.3 ; port I2S_2_SYNC
I2S_2_SYNC_DSI: J12.4 J12B.2 ; port I2S_2_SYNC_DSI
I2S_2_SYNC_M2B: J12.12 J12B.6 ; port I2S_2_SYNC_M2B
PWR_1V8_MOCI: J9.17 J9A.9 ; port PWR_1V8_MOCI
PWR_1V8_MOCI_JMP: J9.18 J9B.9 ; port PWR_1V8_MOCI_JMP
UART_1_CTS: RA38.1 ; port UART_1_CTS
UART_1_CTS_JMP: J8.8 J8B.4 ; port UART_1_CTS_JMP
UART_1_RTS: RA38.2 ; port UART_1_RTS
UART_1_RTS_JMP: J8.6 J8B.3 ; port UART_1_RTS_JMP
UART_1_RXD: RA38.4 ; port UART_1_RXD
UART_1_RXD_JMP: J8.2 J8B.1 ; port UART_1_RXD_JMP
UART_1_TXD: RA38.3 ; port UART_1_TXD
UART_1_TXD_JMP: J8.4 J8B.2 ; port UART_1_TXD_JMP
UART_2_CTS: RA40.1 ; port UART_2_CTS
UART_2_CTS_JMP: J8.16 J8B.8 ; port UART_2_CTS_JMP
UART_2_RTS: RA40.2 ; port UART_2_RTS
UART_2_RTS_JMP: J8.14 J8B.7 ; port UART_2_RTS_JMP
UART_2_RXD: RA40.4 ; port UART_2_RXD
UART_2_RXD_JMP: J8.10 J8B.5 ; port UART_2_RXD_JMP
UART_2_TXD: RA40.3 ; port UART_2_TXD
UART_2_TXD_JMP: J8.12 J8B.6 ; port UART_2_TXD_JMP
UART_3_RXD: RA39.1 ; port UART_3_RXD
UART_3_RXD_JMP: J8.18 J8B.9 ; port UART_3_RXD_JMP
UART_3_TXD: RA39.2 ; port UART_3_TXD
UART_3_TXD_JMP: J8.20 J8B.10 ; port UART_3_TXD_JMP
UART_4_RXD: RA39.3 ; port UART_4_RXD
UART_4_RXD_JMP: J8.22 J8B.11 ; port UART_4_RXD_JMP
UART_4_TXD: RA39.4 ; port UART_4_TXD
UART_4_TXD_JMP: J8.24 J8B.12 ; port UART_4_TXD_JMP
NetJ7_1: J7.1 J7A.1 RA30.8
NetJ7_3: J7.3 J7A.2 RA30.7
NetJ7_5: J7.5 J7A.3 RA30.6
NetJ7_7: J7.7 J7A.4 RA30.5
NetJ7_9: J7.9 J7A.5 RA33.5
NetJ7_11: J7.11 J7A.6 RA33.7
NetJ7_13: J7.13 J7A.7 RA33.6
NetJ7_15: J7.15 J7A.8 RA33.8
NetJ8_1: J8.1 J8A.1 RA38.5
NetJ8_3: J8.3 J8A.2 RA38.6
NetJ8_5: J8.5 J8A.3 RA38.7
NetJ8_7: J8.7 J8A.4 RA38.8
NetJ8_9: J8.9 J8A.5 RA40.5
NetJ8_11: J8.11 J8A.6 RA40.6
NetJ8_13: J8.13 J8A.7 RA40.7
NetJ8_15: J8.15 J8A.8 RA40.8
NetJ8_17: J8.17 J8A.9 RA39.8
NetJ8_19: J8.19 J8A.10 RA39.7
NetJ8_21: J8.21 J8A.11 RA39.6
NetJ8_23: J8.23 J8A.12 RA39.5
NetJ9_1: J9.1 J9A.1 RA34.5
NetJ9_3: J9.3 J9A.2 RA34.6
NetJ9_5: J9.5 J9A.3 RA34.7
NetJ9_7: J9.7 J9A.4 RA34.8
NetJ9_9: J9.9 J9A.5 RA36.5
NetJ9_11: J9.11 J9A.6 RA36.6
NetJ9_13: J9.13 J9A.7 RA36.7
NetJ9_15: J9.15 J9A.8 RA36.8
NetJ10_1: J10.1 J10A.1 RA15.4
NetJ10_3: J10.3 J10A.2 RA15.3
NetJ11_1: J11.1 J11A.1 RA45.5
NetJ11_3: J11.3 J11A.2 RA45.6
NetJ11_5: J11.5 J11A.3 RA45.7
NetJ11_7: J11.7 J11A.4 RA45.8
NetJ12_1: J12.1 J12.9 J12A.1 J12A.5 RA22.5
NetJ12_3: J12.3 J12.11 J12A.2 J12A.6 RA22.6
NetJ12_5: J12.5 J12.13 J12A.3 J12A.7 RA22.7
NetJ12_7: J12.7 J12.15 J12A.4 J12A.8 RA22.8

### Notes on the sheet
- Jumpers
- DP_HPD Jumper
- 1-2: HPD connected to AQUILA_B59
- (near J92) Unconnected: HPD disconnected

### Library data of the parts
J7 J9 J12 = 2203-Conn-Hdr 2x10 2.54MM: as J1 on sheet 800_Jumpers
J7A J7B J9A J9B J12A J12B J13 = 2202-Conn-Hdr 1x10 2.54MM F: as J60 on sheet 215_Translators2
J8 = 2206-Conn-Hdr 2x12 2.54MM: as J4 on sheet 800_Jumpers
J8A J8B = 2221-Conn-Hdr 1x12 2.54MM F: as J4A on sheet 800_Jumpers
J10 J11 = 2532-Conn-Hdr 2x4 2.54MM: as J19 on sheet 225_Debug2
J10A J10B J11A J11B = 2191-Conn-Hdr 1x4 2.54MM F: (-40 to 125 DegC) CONN HEADER FEMALE 1x4 4POS 2.54MM TH; Mfr: Wurth Electronics; PN: 2191
J92 = 1250-Conn-Hdr-1x2 TH Vert: as J63 on sheet 225_Debug2
R413 R414 R426 R427 R477 R478 = 1536-Res-0402-1.87K: as R75 on sheet 800_Jumpers
RA15 = 1265-ResArr-22ohm: as RA1 on sheet 800_Jumpers
RA22 RA30 RA33 RA34 RA36 RA38-RA40 RA45 = 1848-ResArr-0804-22ohm: as RA14 on sheet 800_Jumpers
